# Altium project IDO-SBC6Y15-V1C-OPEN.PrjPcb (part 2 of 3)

## Sheet P06 SOM6ULX.SchDoc
size 594 x 420 mm
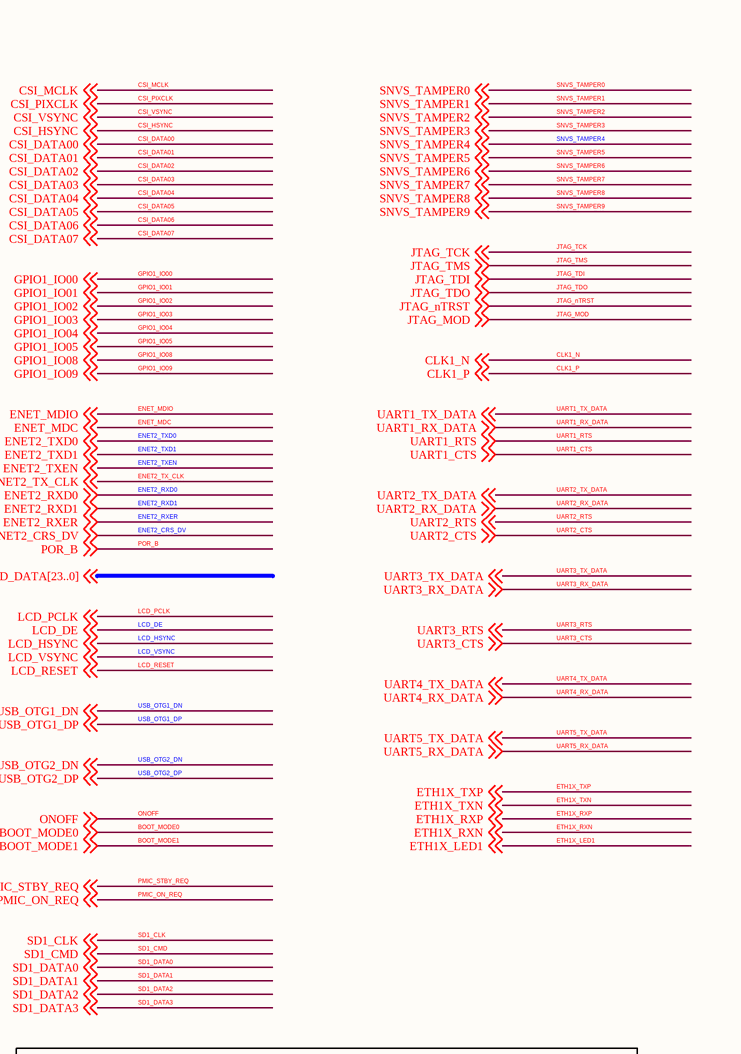
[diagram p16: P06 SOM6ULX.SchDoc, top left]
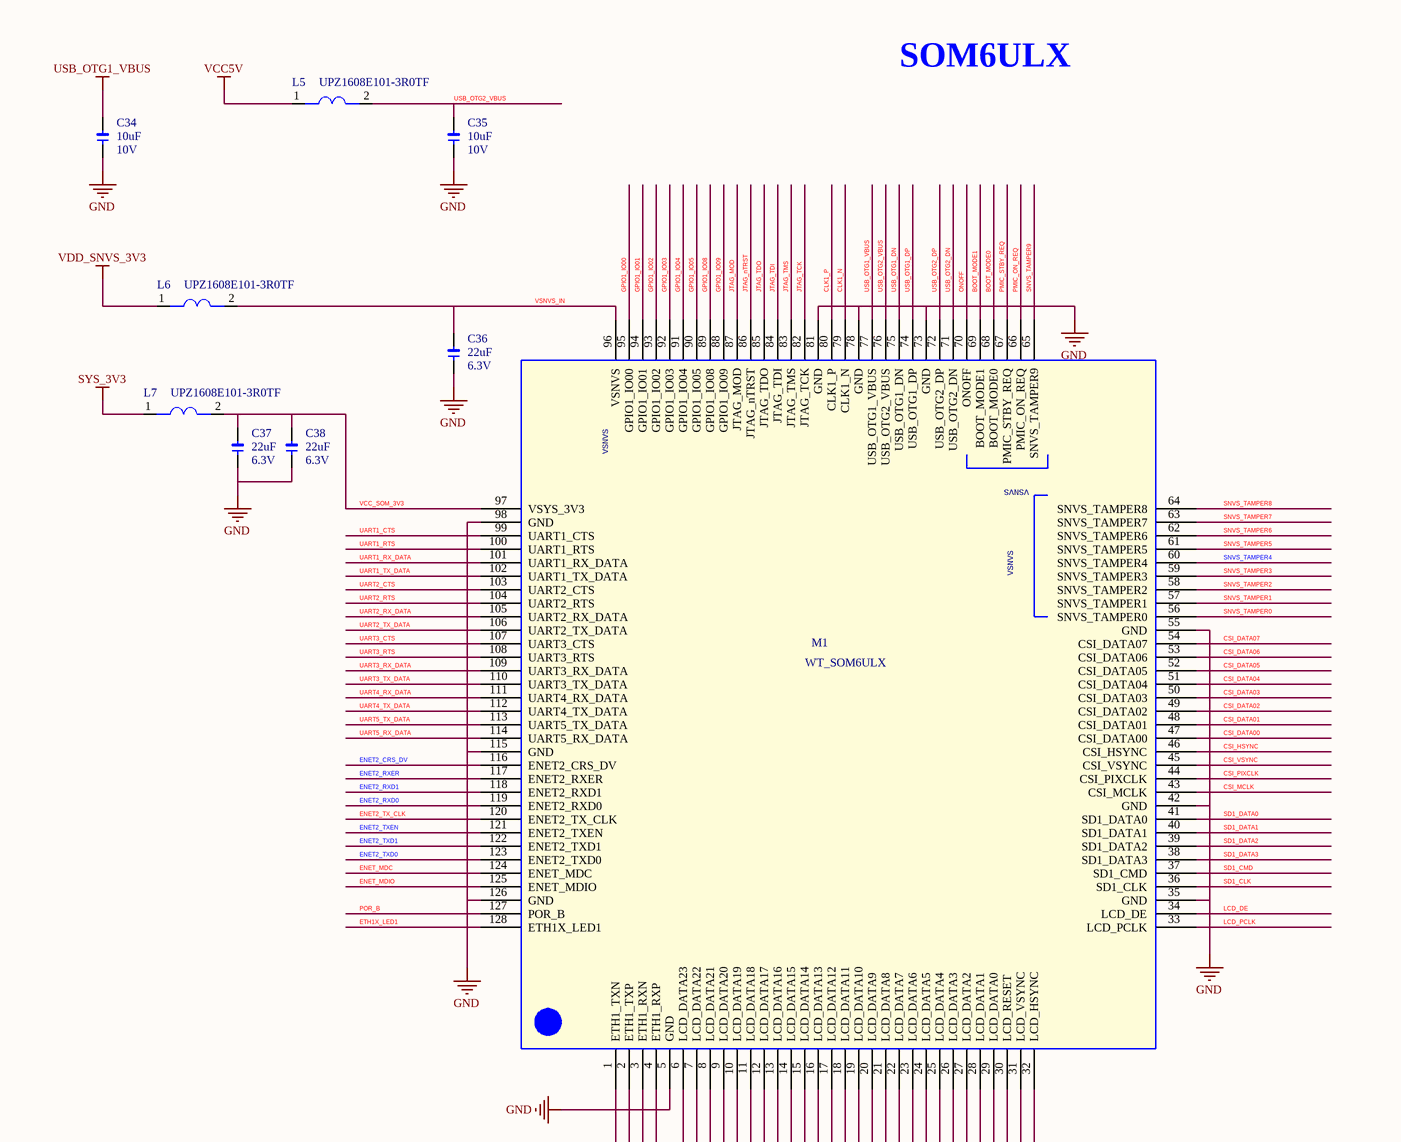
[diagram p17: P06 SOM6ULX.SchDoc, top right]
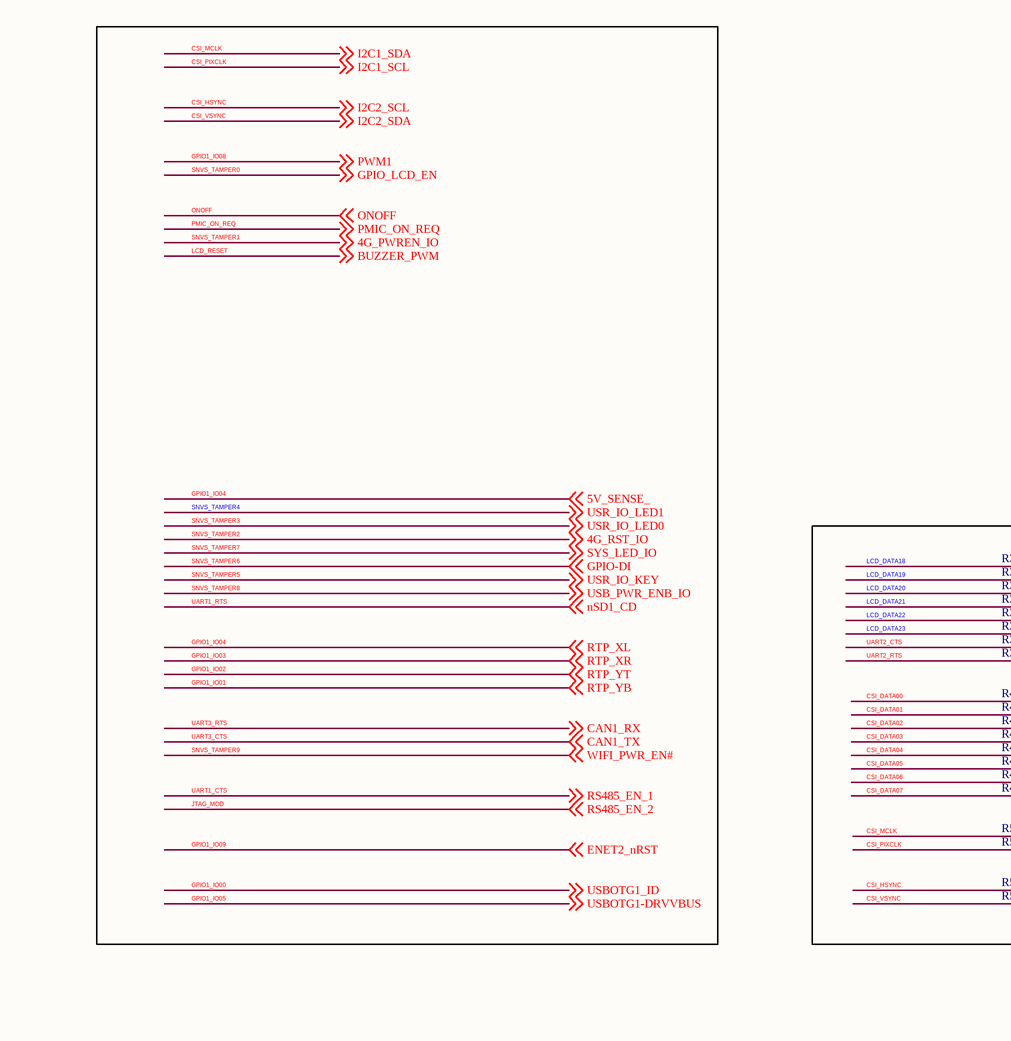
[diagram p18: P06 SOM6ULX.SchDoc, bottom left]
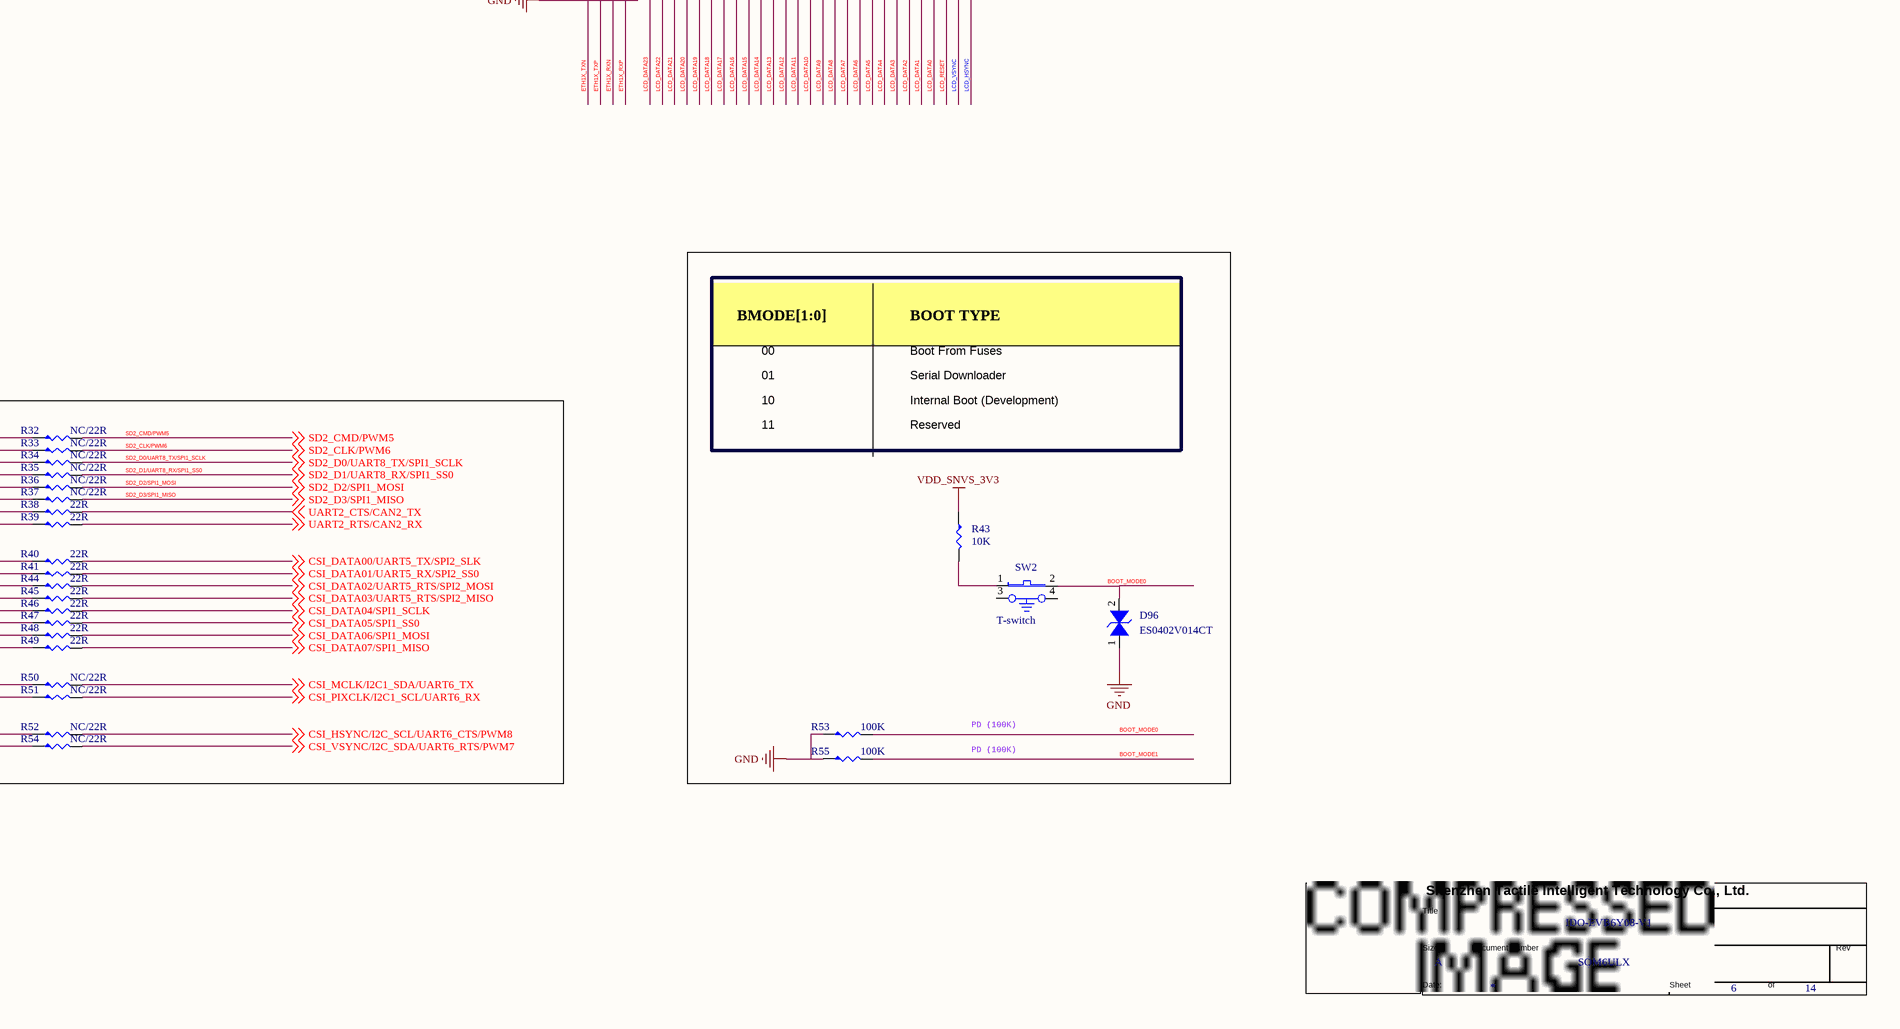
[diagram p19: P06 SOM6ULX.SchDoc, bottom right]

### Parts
(Parts that share a designator on the sheet are numbered #1, #2 ... from top to bottom, then left to right.)
*#6  Doc: SOM6ULX  Title: IDO-EVB6Y08-V1  Page Size: A  Page Number: 6  Page Count: 14  (hidden comment: TitleBlock1)  (graphical)
C34  10uF  DSC2: 10V  [1206]
C35  10uF  DSC2: 10V  [1206]
C36  22uF  DSC2: 6.3V  [1206]
C37  22uF  DSC2: 6.3V  [1206]
C38  22uF  DSC2: 6.3V  [1206]
D96  ES0402V014CT  [V0402]
L5  UPZ1608E101-3R0TF  [L0603]
L6  UPZ1608E101-3R0TF  [L0603]
L7  UPZ1608E101-3R0TF  [L0603]
M1  WT_SOM6ULX  [WT_SOM6ULX_LGA128]
R32  NC/22R  [R0402L]
R33  NC/22R  [R0402L]
R34  NC/22R  [R0402L]
R35  NC/22R  [R0402L]
R36  NC/22R  [R0402L]
R37  NC/22R  [R0402L]
R38  22R  [R0402L]
R39  22R  [R0402L]
R40  22R  [R0402L]
R41  22R  [R0402L]
R43  10K  [R0402L]
R44  22R  [R0402L]
R45  22R  [R0402L]
R46  22R  [R0402L]
R47  22R  [R0402L]
R48  22R  [R0402L]
R49  22R  [R0402L]
R50  NC/22R  [R0402L]
R51  NC/22R  [R0402L]
R52  NC/22R  [R0402L]
R53  100K  [R0402L]
R54  NC/22R  [R0402L]
R55  100K  [R0402L]
SW2  T-switch  [PB-SIDE-S-3x6]

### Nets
GND: C34.1 C35.1 C36.1 C37.1 C38.1 D96.1(I/O2) M1.5(GND) M1.35(GND) M1.42(GND) M1.55(GND) M1.73(GND) M1.78(GND) M1.81(GND) M1.98(GND) M1.115(GND) M1.126(GND) R53.1 R55.1
SYS_3V3: L7.1
USB_OTG1_VBUS: C34.2 M1.77(USB_OTG1_VBUS)
VCC5V: L5.1
VDD_SNVS_3V3: L6.1 R43.1
4G_PWREN_IO: M1.57(SNVS_TAMPER1) ; off-sheet 4G_PWREN_IO, off-sheet SNVS_TAMPER1  [also labelled SNVS_TAMPER1]  [project net 4G_POWER_EN]
4G_RST_IO: M1.58(SNVS_TAMPER2) ; off-sheet 4G_RST_IO, off-sheet SNVS_TAMPER2  [also labelled SNVS_TAMPER2]  [project net 4G_RST]
5V_SENSE_: M1.91(GPIO1_IO04) ; off-sheet RTP_XL, off-sheet GPIO1_IO04, off-sheet 5V_SENSE_  [also labelled GPIO1_IO04, RTP_XL]
BOOT_MODE0: D96.2(I/O1) M1.68(BOOT_MODE0) R53.2 SW2.2 ; off-sheet BOOT_MODE0
BOOT_MODE1: M1.69(BOOT_MODE1) R55.2 ; off-sheet BOOT_MODE1
BUZZER_PWM: M1.30(LCD_RESET) ; off-sheet BUZZER_PWM, off-sheet LCD_RESET  [also labelled LCD_RESET]
CAN1_RX: M1.108(UART3_RTS) ; off-sheet CAN1_RX, off-sheet UART3_RTS  [also labelled UART3_RTS]
CAN1_TX: M1.107(UART3_CTS) ; off-sheet CAN1_TX, off-sheet UART3_CTS  [also labelled UART3_CTS]
CLK1_N: M1.79(CLK1_N) ; off-sheet CLK1_N
CLK1_P: M1.80(CLK1_P) ; off-sheet CLK1_P
CSI_DATA00: M1.47(CSI_DATA00) R40.1 ; off-sheet CSI_DATA00
CSI_DATA00/UART5_TX/SPI2_SLK: R40.2 ; off-sheet CSI_DATA00/UART5_TX/SPI2_SLK
CSI_DATA01: M1.48(CSI_DATA01) R41.1 ; off-sheet CSI_DATA01
CSI_DATA01/UART5_RX/SPI2_SS0: R41.2 ; off-sheet CSI_DATA01/UART5_RX/SPI2_SS0
CSI_DATA02: M1.49(CSI_DATA02) R44.1 ; off-sheet CSI_DATA02
CSI_DATA02/UART5_RTS/SPI2_MOSI: R44.2 ; off-sheet CSI_DATA02/UART5_RTS/SPI2_MOSI
CSI_DATA03: M1.50(CSI_DATA03) R45.1 ; off-sheet CSI_DATA03
CSI_DATA03/UART5_RTS/SPI2_MISO: R45.2 ; off-sheet CSI_DATA03/UART5_RTS/SPI2_MISO
CSI_DATA04: M1.51(CSI_DATA04) R46.1 ; off-sheet CSI_DATA04
CSI_DATA04/SPI1_SCLK: R46.2 ; off-sheet CSI_DATA04/SPI1_SCLK
CSI_DATA05: M1.52(CSI_DATA05) R47.1 ; off-sheet CSI_DATA05
CSI_DATA05/SPI1_SS0: R47.2 ; off-sheet CSI_DATA05/SPI1_SS0
CSI_DATA06: M1.53(CSI_DATA06) R48.1 ; off-sheet CSI_DATA06
CSI_DATA06/SPI1_MOSI: R48.2 ; off-sheet CSI_DATA06/SPI1_MOSI
CSI_DATA07: M1.54(CSI_DATA07) R49.1 ; off-sheet CSI_DATA07
CSI_DATA07/SPI1_MISO: R49.2 ; off-sheet CSI_DATA07/SPI1_MISO
CSI_HSYNC: M1.46(CSI_HSYNC) R52.1 ; off-sheet I2C2_SCL, off-sheet CSI_HSYNC  [also labelled I2C2_SCL]
CSI_HSYNC/I2C_SCL/UART6_CTS/PWM8: R52.2 ; off-sheet CSI_HSYNC/I2C_SCL/UART6_CTS/PWM8
CSI_MCLK: M1.43(CSI_MCLK) R50.1 ; off-sheet I2C1_SDA, off-sheet CSI_MCLK  [also labelled I2C1_SDA]
CSI_MCLK/I2C1_SDA/UART6_TX: R50.2 ; off-sheet CSI_MCLK/I2C1_SDA/UART6_TX
CSI_PIXCLK: M1.44(CSI_PIXCLK) R51.1 ; off-sheet I2C1_SCL, off-sheet CSI_PIXCLK  [also labelled I2C1_SCL]
CSI_PIXCLK/I2C1_SCL/UART6_RX: R51.2 ; off-sheet CSI_PIXCLK/I2C1_SCL/UART6_RX
CSI_VSYNC: M1.45(CSI_VSYNC) R54.1 ; off-sheet I2C2_SDA, off-sheet CSI_VSYNC  [also labelled I2C2_SDA]
CSI_VSYNC/I2C_SDA/UART6_RTS/PWM7: R54.2 ; off-sheet CSI_VSYNC/I2C_SDA/UART6_RTS/PWM7
ENET2_CRS_DV: M1.116(ENET2_CRS_DV) ; off-sheet ENET2_CRS_DV
ENET2_nRST: M1.88(GPIO1_IO09) ; off-sheet ENET2_nRST, off-sheet GPIO1_IO09  [also labelled GPIO1_IO09]
ENET2_RXD0: M1.119(ENET2_RXD0) ; off-sheet ENET2_RXD0
ENET2_RXD1: M1.118(ENET2_RXD1) ; off-sheet ENET2_RXD1
ENET2_RXER: M1.117(ENET2_RXER) ; off-sheet ENET2_RXER
ENET2_TX_CLK: M1.120(ENET2_TX_CLK) ; off-sheet ENET2_TX_CLK
ENET2_TXD0: M1.123(ENET2_TXD0) ; off-sheet ENET2_TXD0
ENET2_TXD1: M1.122(ENET2_TXD1) ; off-sheet ENET2_TXD1
ENET2_TXEN: M1.121(ENET2_TXEN) ; off-sheet ENET2_TXEN
ENET_MDC: M1.124(ENET_MDC) ; off-sheet ENET_MDC
ENET_MDIO: M1.125(ENET_MDIO) ; off-sheet ENET_MDIO
ETH1X_LED1: M1.128(ETH1X_LED1) ; off-sheet ETH1X_LED1
ETH1X_RXN: M1.3(ETH1_RXN) ; off-sheet ETH1X_RXN
ETH1X_RXP: M1.4(ETH1_RXP) ; off-sheet ETH1X_RXP
ETH1X_TXN: M1.1(ETH1_TXN) ; off-sheet ETH1X_TXN
ETH1X_TXP: M1.2(ETH1_TXP) ; off-sheet ETH1X_TXP
GPIO1_IO00: M1.95(GPIO1_IO00) ; off-sheet USBOTG1_ID, off-sheet GPIO1_IO00  [also labelled USBOTG1_ID]
GPIO1_IO01: M1.94(GPIO1_IO01) ; off-sheet RTP_YB, off-sheet GPIO1_IO01  [also labelled RTP_YB]
GPIO1_IO02: M1.93(GPIO1_IO02) ; off-sheet RTP_YT, off-sheet GPIO1_IO02  [also labelled RTP_YT]
GPIO1_IO03: M1.92(GPIO1_IO03) ; off-sheet RTP_XR, off-sheet GPIO1_IO03  [also labelled RTP_XR]
GPIO1_IO05: M1.90(GPIO1_IO05) ; off-sheet USBOTG1-DRVVBUS, off-sheet GPIO1_IO05  [also labelled USBOTG1-DRVVBUS]
GPIO1_IO08: M1.89(GPIO1_IO08) ; off-sheet PWM1, off-sheet GPIO1_IO08  [also labelled PWM1]
GPIO-DI: M1.62(SNVS_TAMPER6) ; off-sheet GPIO-DI, off-sheet SNVS_TAMPER6  [also labelled SNVS_TAMPER6]
GPIO_LCD_EN: M1.56(SNVS_TAMPER0) ; off-sheet GPIO_LCD_EN, off-sheet SNVS_TAMPER0  [also labelled SNVS_TAMPER0]
JTAG_MOD: M1.87(JTAG_MOD) ; off-sheet RS485_EN_2, off-sheet JTAG_MOD  [also labelled RS485_EN_2]
JTAG_nTRST: M1.86(JTAG_nTRST) ; off-sheet JTAG_nTRST
JTAG_TCK: M1.82(JTAG_TCK) ; off-sheet JTAG_TCK
JTAG_TDI: M1.84(JTAG_TDI) ; off-sheet JTAG_TDI
JTAG_TDO: M1.85(JTAG_TDO) ; off-sheet JTAG_TDO
JTAG_TMS: M1.83(JTAG_TMS) ; off-sheet JTAG_TMS
LCD_DATA0: M1.29(LCD_DATA0)
LCD_DATA1: M1.28(LCD_DATA1)
LCD_DATA2: M1.27(LCD_DATA2)
LCD_DATA3: M1.26(LCD_DATA3)
LCD_DATA4: M1.25(LCD_DATA4)
LCD_DATA5: M1.24(LCD_DATA5)
LCD_DATA6: M1.23(LCD_DATA6)
LCD_DATA7: M1.22(LCD_DATA7)
LCD_DATA8: M1.21(LCD_DATA8)
LCD_DATA9: M1.20(LCD_DATA9)
LCD_DATA10: M1.19(LCD_DATA10)
LCD_DATA11: M1.18(LCD_DATA11)
LCD_DATA12: M1.17(LCD_DATA12)
LCD_DATA13: M1.16(LCD_DATA13)
LCD_DATA14: M1.15(LCD_DATA14)
LCD_DATA15: M1.14(LCD_DATA15)
LCD_DATA16: M1.13(LCD_DATA16)
LCD_DATA17: M1.12(LCD_DATA17)
LCD_DATA18: M1.11(LCD_DATA18) R32.1
LCD_DATA19: M1.10(LCD_DATA19) R33.1
LCD_DATA20: M1.9(LCD_DATA20) R34.1
LCD_DATA21: M1.8(LCD_DATA21) R35.1
LCD_DATA22: M1.7(LCD_DATA22) R36.1
LCD_DATA23: M1.6(LCD_DATA23) R37.1
LCD_DE: M1.34(LCD_DE) ; off-sheet LCD_DE
LCD_HSYNC: M1.32(LCD_HSYNC) ; off-sheet LCD_HSYNC
LCD_PCLK: M1.33(LCD_PCLK) ; off-sheet LCD_PCLK
LCD_VSYNC: M1.31(LCD_VSYNC) ; off-sheet LCD_VSYNC
ONOFF: M1.70(ONOFF) ; off-sheet ONOFF
PMIC_ON_REQ: M1.66(PMIC_ON_REQ) ; off-sheet PMIC_ON_REQ
PMIC_STBY_REQ: M1.67(PMIC_STBY_REQ) ; off-sheet PMIC_STBY_REQ
POR_B: M1.127(POR_B) ; off-sheet POR_B
RS485_EN_1: M1.99(UART1_CTS) ; off-sheet RS485_EN_1, off-sheet UART1_CTS  [also labelled UART1_CTS]
SD1_CLK: M1.36(SD1_CLK) ; off-sheet SD1_CLK
SD1_CMD: M1.37(SD1_CMD) ; off-sheet SD1_CMD
SD1_DATA0: M1.41(SD1_DATA0) ; off-sheet SD1_DATA0
SD1_DATA1: M1.40(SD1_DATA1) ; off-sheet SD1_DATA1
SD1_DATA2: M1.39(SD1_DATA2) ; off-sheet SD1_DATA2
SD1_DATA3: M1.38(SD1_DATA3) ; off-sheet SD1_DATA3
SD2_CLK/PWM6: R33.2 ; off-sheet SD2_CLK/PWM6
SD2_CMD/PWM5: R32.2 ; off-sheet SD2_CMD/PWM5
SD2_D0/UART8_TX/SPI1_SCLK: R34.2 ; off-sheet SD2_D0/UART8_TX/SPI1_SCLK
SD2_D1/UART8_RX/SPI1_SS0: R35.2 ; off-sheet SD2_D1/UART8_RX/SPI1_SS0
SD2_D2/SPI1_MOSI: R36.2 ; off-sheet SD2_D2/SPI1_MOSI
SD2_D3/SPI1_MISO: R37.2 ; off-sheet SD2_D3/SPI1_MISO
SNVS_TAMPER3: M1.59(SNVS_TAMPER3) ; off-sheet USR_IO_LED0, off-sheet SNVS_TAMPER3  [also labelled USR_IO_LED0]
SNVS_TAMPER4: M1.60(SNVS_TAMPER4) ; off-sheet USR_IO_LED1, off-sheet SNVS_TAMPER4  [also labelled USR_IO_LED1]
SNVS_TAMPER5: M1.61(SNVS_TAMPER5) ; off-sheet USR_IO_KEY, off-sheet SNVS_TAMPER5  [also labelled USR_IO_KEY]  [project net IO_KEY]
SNVS_TAMPER7: M1.63(SNVS_TAMPER7) ; off-sheet SYS_LED_IO, off-sheet SNVS_TAMPER7  [also labelled SYS_LED_IO]
SNVS_TAMPER8: M1.64(SNVS_TAMPER8) ; off-sheet USB_PWR_ENB_IO, off-sheet SNVS_TAMPER8  [also labelled USB_PWR_ENB_IO]
SNVS_TAMPER9: M1.65(SNVS_TAMPER9) ; off-sheet WIFI_PWR_EN#, off-sheet SNVS_TAMPER9  [also labelled WIFI_PWR_EN#]
UART1_RTS: M1.100(UART1_RTS) ; off-sheet nSD1_CD, off-sheet UART1_RTS  [also labelled nSD1_CD]
UART1_RX_DATA: M1.101(UART1_RX_DATA) ; off-sheet UART1_RX_DATA
UART1_TX_DATA: M1.102(UART1_TX_DATA) ; off-sheet UART1_TX_DATA
UART2_CTS: M1.103(UART2_CTS) R38.1 ; off-sheet UART2_CTS
UART2_CTS/CAN2_TX: R38.2 ; off-sheet UART2_CTS/CAN2_TX
UART2_RTS: M1.104(UART2_RTS) R39.1 ; off-sheet UART2_RTS
UART2_RTS/CAN2_RX: R39.2 ; off-sheet UART2_RTS/CAN2_RX
UART2_RX_DATA: M1.105(UART2_RX_DATA) ; off-sheet UART2_RX_DATA
UART2_TX_DATA: M1.106(UART2_TX_DATA) ; off-sheet UART2_TX_DATA
UART3_RX_DATA: M1.109(UART3_RX_DATA) ; off-sheet UART3_RX_DATA
UART3_TX_DATA: M1.110(UART3_TX_DATA) ; off-sheet UART3_TX_DATA
UART4_RX_DATA: M1.111(UART4_RX_DATA) ; off-sheet UART4_RX_DATA  [project net RS485X1_DOUT]
UART4_TX_DATA: M1.112(UART4_TX_DATA) ; off-sheet UART4_TX_DATA  [project net RS485X1_DIN]
UART5_RX_DATA: M1.114(UART5_RX_DATA) ; off-sheet UART5_RX_DATA  [project net RS485X2_DOUT]
UART5_TX_DATA: M1.113(UART5_TX_DATA) ; off-sheet UART5_TX_DATA  [project net RS485X2_DIN]
USB_OTG1_DN: M1.75(USB_OTG1_DN) ; off-sheet USB_OTG1_DN
USB_OTG1_DP: M1.74(USB_OTG1_DP) ; off-sheet USB_OTG1_DP
USB_OTG2_DN: M1.71(USB_OTG2_DN) ; off-sheet USB_OTG2_DN
USB_OTG2_DP: M1.72(USB_OTG2_DP) ; off-sheet USB_OTG2_DP
USB_OTG2_VBUS: C35.2 L5.2 M1.76(USB_OTG2_VBUS)
VCC_SOM_3V3: C37.2 C38.2 L7.2 M1.97(VSYS_3V3)
VSNVS_IN: C36.2 L6.2 M1.96(VSNVS)
NetR43_2: R43.2 SW2.1

Not connected (* = marked no-connect by the designer): SW2 3 4

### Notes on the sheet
- SOM6ULX
- BMODE[1:0]
- BOOT TYPE
- 00
- 01
- 10
- Boot From Fuses
- Serial Downloader
- Internal Boot (Development)
- 11
- Reserved
- PD (100K)

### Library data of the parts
C34 = C-0603: Manufacture: 三星¦国巨¦村田; Part Name: 贴片电容; Part Number: C020102120071; ID: 71; DSC3: X5R; DSC1: ±20%; ERP Number: 1010200076; PCB Footprint: C0603L
C35 = C-0603: Part Number: C020102120071; Part Name: 贴片电容; Manufacture: 三星¦国巨¦村田; ERP Number: 1010200076; DSC1: ±20%; DSC3: X5R; ID: 71; PCB Footprint: C0603L
C36-C38 = C-0603: Manufacture: 三星¦国巨¦村田; Part Name: 贴片电容; Part Number: C020102120072; ID: 72; DSC3: X5R; DSC1: ±20%; ERP Number: 1010200133; PCB Footprint: C0603L
D96 = DI-ESD: ESD 0402; Part Number: C040502250002; Manufacture P/N: MLVG04021R0UV18; Manufacturer: INPAQ; Manufacture: AEM; PN Type: Varistor; ERP Number: 1010800023; DSC1: 双向; DSC2: Vdc=14V; DSC3: Vbr=300V; DSC4: Vc=30V; DSC5: Cj=0.25pF; ID: 2
L5 L7 = FB-0603: SMD Multilayer Ferrite Chip Bead,3A,30Ohm,0.03R; Manufacturer: SUNLORD; Manufacture2 P/N: PBY160808T-400Y-N; Manufacture P/N: PZ1608D300-3R0TF; Part Number: C060502370005; Manufacture: 顺络; Part Name: 贴片磁珠; PN Type: SMD FERRITE BEAD; ID: 5; DSC4: 电源线; DSC3: DCR=30mΩ; DSC1: 100Ω@100MHz; ERP Number: 1010200207
L6 = FB-0603: SMD Multilayer Ferrite Chip Bead,3A,30Ohm,0.03R; Manufacturer: SUNLORD; Manufacture2 P/N: PBY160808T-400Y-N; Manufacture P/N: PZ1608D300-3R0TF; Part Number: C060502370005; Part Name: 贴片磁珠; Manufacture: 顺络; PN Type: SMD FERRITE BEAD; ERP Number: 1010200207; DSC1: 100Ω@100MHz; DSC3: DCR=30mΩ; DSC4: 电源线; ID: 5
M1 = IDO-SOM6Y08
R32-R37 R40 R41 R44-R51 = R-0402: Part Number: C011002080552; Part Name: 贴片电阻; ID: 552; DSC2: 1/16W; DSC1: ±1%
R38 R39 R52 R54 = R-0402: Part Name: 贴片电阻; Part Number: C011002080552; DSC1: ±1%; DSC2: 1/16W; ID: 552
R43 = R-0402: Part Name: 贴片电阻; Part Number: C011002080856; ERP Number: 1010200140; DSC1: ±1%; DSC2: 1/16W; ID: 856
R53 R55 = R-0402: Part Number: C011002080976; Part Name: 贴片电阻; ID: 976; DSC2: 1/16W; DSC1: ±1%; ERP Number: 1010200137
SW2 = SW-TS36CA: Part Number: C180102690002; Part Name: 轻触开关; DSC1: 轻触开关 侧键 贴片 带定位柱; DSC2: SMD,3.5*7.7mm; DSC3: TS36CA-0.7(首韩); DSC4: TSA365G00D-250(博瑞泰); ID: 2

## Sheet P07 SD_RTC.SchDoc
size 594 x 420 mm
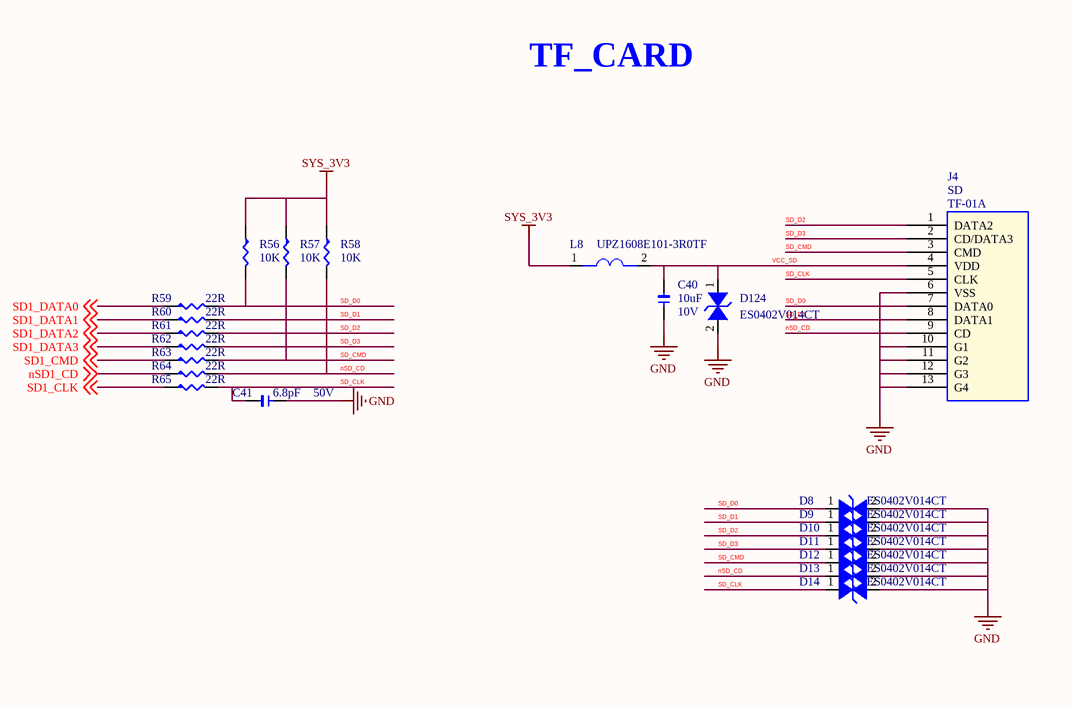
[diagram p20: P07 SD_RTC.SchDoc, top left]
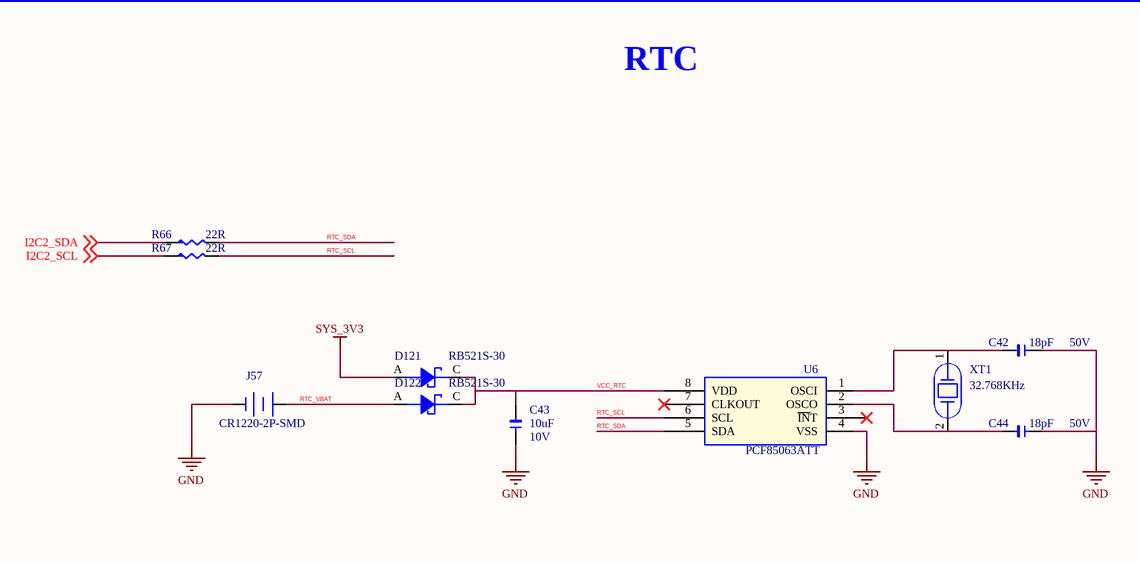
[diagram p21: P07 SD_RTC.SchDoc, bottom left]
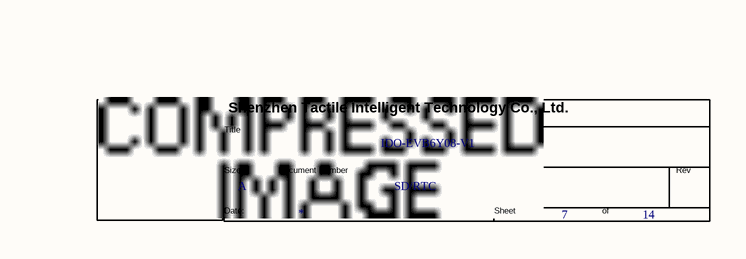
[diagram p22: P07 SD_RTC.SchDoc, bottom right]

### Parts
(Parts that share a designator on the sheet are numbered #1, #2 ... from top to bottom, then left to right.)
*#7  Doc: SD/RTC  Title: IDO-EVB6Y08-V1  Page Size: A  Page Number: 7  Page Count: 14  (hidden comment: TitleBlock1)  (graphical)
C40  10uF  DSC2: 10V  [1206]
C41  6.8pF  DSC2: 50V  [1206]
C42  18pF  DSC2: 50V  [1206]
C43  10uF  DSC2: 10V  [1206]
C44  18pF  DSC2: 50V  [1206]
D8  ES0402V014CT  [V0402]
D9  ES0402V014CT  [V0402]
D10  ES0402V014CT  [V0402]
D11  ES0402V014CT  [V0402]
D12  ES0402V014CT  [V0402]
D13  ES0402V014CT  [V0402]
D14  ES0402V014CT  [V0402]
D121  RB521S-30  [SOD523]
D122  RB521S-30  [SOD523]
D124  ES0402V014CT  [V0402]
J4  SD  [TF-01A]
J57  CR1220-2P-SMD  [CR1220-2P-SMD]
L8  UPZ1608E101-3R0TF  [L0603]
R56  10K  [R0402L]
R57  10K  [R0402L]
R58  10K  [R0402L]
R59  22R  [R0402L]
R60  22R  [R0402L]
R61  22R  [R0402L]
R62  22R  [R0402L]
R63  22R  [R0402L]
R64  22R  [R0402L]
R65  22R  [R0402L]
R66  22R  [R0402L]
R67  22R  [R0402L]
U6  PCF85063ATT  [PCF85063ATT-TSSOP8]
XT1  32.768KHz  [XTAL_32X15_2P]

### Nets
GND: C40.1 C41.1 C42.1 C43.1 C44.1 D8.2(I/O1) D9.2(I/O1) D10.2(I/O1) D11.2(I/O1) D12.2(I/O1) D13.2(I/O1) D14.2(I/O1) D124.2(I/O1) J4.6(VSS) J4.10(G1) J4.11(G2) J4.12(G3) J4.13(G4) J57.2(-) U6.4(VSS)
SYS_3V3: D121.A L8.1 R56.1 R57.1 R58.1
I2C2_SCL: R67.1 ; off-sheet I2C2_SCL  [project net CSI_HSYNC]
I2C2_SDA: R66.1 ; off-sheet I2C2_SDA  [project net CSI_VSYNC]
nSD1_CD: R64.1 ; off-sheet nSD1_CD  [project net UART1_RTS]
nSD_CD: D13.1(I/O2) J4.9(CD) R58.2 R64.2
RTC_SCL: R67.2 U6.6(SCL)
RTC_SDA: R66.2 U6.5(SDA)
RTC_VBAT: D122.A J57.1(+)
SD1_CLK: R65.1 ; off-sheet SD1_CLK
SD1_CMD: R63.1 ; off-sheet SD1_CMD
SD1_DATA0: R59.1 ; off-sheet SD1_DATA0
SD1_DATA1: R60.1 ; off-sheet SD1_DATA1
SD1_DATA2: R61.1 ; off-sheet SD1_DATA2
SD1_DATA3: R62.1 ; off-sheet SD1_DATA3
SD_CLK: C41.2 D14.1(I/O2) J4.5(CLK) R65.2
SD_CMD: D12.1(I/O2) J4.3(CMD) R57.2 R63.2
SD_D0: D8.1(I/O2) J4.7(DATA0) R56.2 R59.2
SD_D1: D9.1(I/O2) J4.8(DATA1) R60.2
SD_D2: D10.1(I/O2) J4.1(DATA2) R61.2
SD_D3: D11.1(I/O2) J4.2(CD/DATA3) R62.2
VCC_RTC: C43.2 D121.C D122.C U6.8(VDD)
VCC_SD: C40.2 D124.1(I/O2) J4.4(VDD) L8.2
NetC42_2: C42.2 U6.1(OSCI) XT1.1
NetC44_2: C44.2 U6.2(OSCO) XT1.2

Not connected (* = marked no-connect by the designer): U6 3(~{IN}T)* 7(CLKOUT)*

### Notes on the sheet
- TF_CARD
- RTC

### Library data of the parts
C40 = C-0603: as C35 on sheet P06 SOM6ULX
C41 = C-0402: Part Number: C020102120018; Part Name: 贴片电容; Manufacture: 三星¦国巨¦村田; PCB Footprint: C0402L; ERP Number: 1010200056; DSC1: ±0.25PF; DSC3: C0G; ID: 18
C42 C44 = C-0402: Manufacture: 三星¦国巨¦村田; Part Name: 贴片电容; Part Number: C020102120027; PCB Footprint: C0402L; ID: 27; DSC3: C0G; DSC1: ±5%; ERP Number: 1010200091
C43 = C-0603: Manufacture: 三星¦国巨¦村田; Part Name: 贴片电容; Part Number: C020102120071; PCB Footprint: C0603L; ID: 71; DSC3: X5R; DSC1: ±20%; ERP Number: 1010200076
D8-D12 = DI-ESD: ESD 0402; Part Number: C040502250002; Manufacture P/N: MLVG04021R0UV18; Manufacturer: INPAQ; Manufacture: AEM; PN Type: Varistor; ID: 2; DSC5: Cj=0.25pF; DSC4: Vc=30V; DSC3: Vbr=300V; DSC2: Vdc=14V; DSC1: 双向; ERP Number: 1010800023
D13 D14 D124 = DI-ESD: as D96 on sheet P06 SOM6ULX
D121 D122 = DI-XI-S: Part Number: C040202220015; Part Name: 肖特基二级管; Manufacture: 长电; CLASS: IC; ERP Number: 1010800004; DSC1: VR=30V; DSC2: IF=200mA; DSC3: VF=100mV/10mA; DSC4: IR=30uA; ID: 15; Solder: 量产
J4 = J-TF-01A: Part Name: SD卡座; Part Number: J080102980002; ID: 2; DSC4: TF-01A(韩荣); DSC3: 贴片; DSC1: TF卡座 自弹式
J57 = RTC-CR1220-2P-SMD: Part Name: 电池座; Part Number: J100303030001; ID: 4; DSC3: 贴片; DSC1: CR1220电池座 贴片 双定位柱; ERP Number: 1040100045
L8 = FB-0603: as L5 on sheet P06 SOM6ULX
R56-R58 = R-0402: Part Number: C011002080856; Part Name: 贴片电阻; ID: 856; DSC2: 1/16W; DSC1: ±1%; ERP Number: 1010200140
R59 R66 R67 = R-0402: as R32-R37 on sheet P06 SOM6ULX
R60-R65 = R-0402: as R38 on sheet P06 SOM6ULX
U6 = U-PCF85063ATT: Manufacture: NXP; Part Name: RTC芯片; Part Number: C110203283829; ID: 14; DSC3: -40℃~+85℃; DSC2: TSSOP8; DSC1: RTC,I2C, VCC=0.9-5.5V
XT1 = XTAL-2P: Manufacture: 泰晶; Part Number: C050102290002; Part Name: 贴片无源晶振; CLASS: IC; ID: 2; DSC5: 3.2*1.5mm 2P; DSC4: -40℃~+85℃; DSC3: 12.5pF; DSC2: ±20ppm; DSC1: 70kΩ

## Sheet P08 USB.SchDoc
size 594 x 420 mm
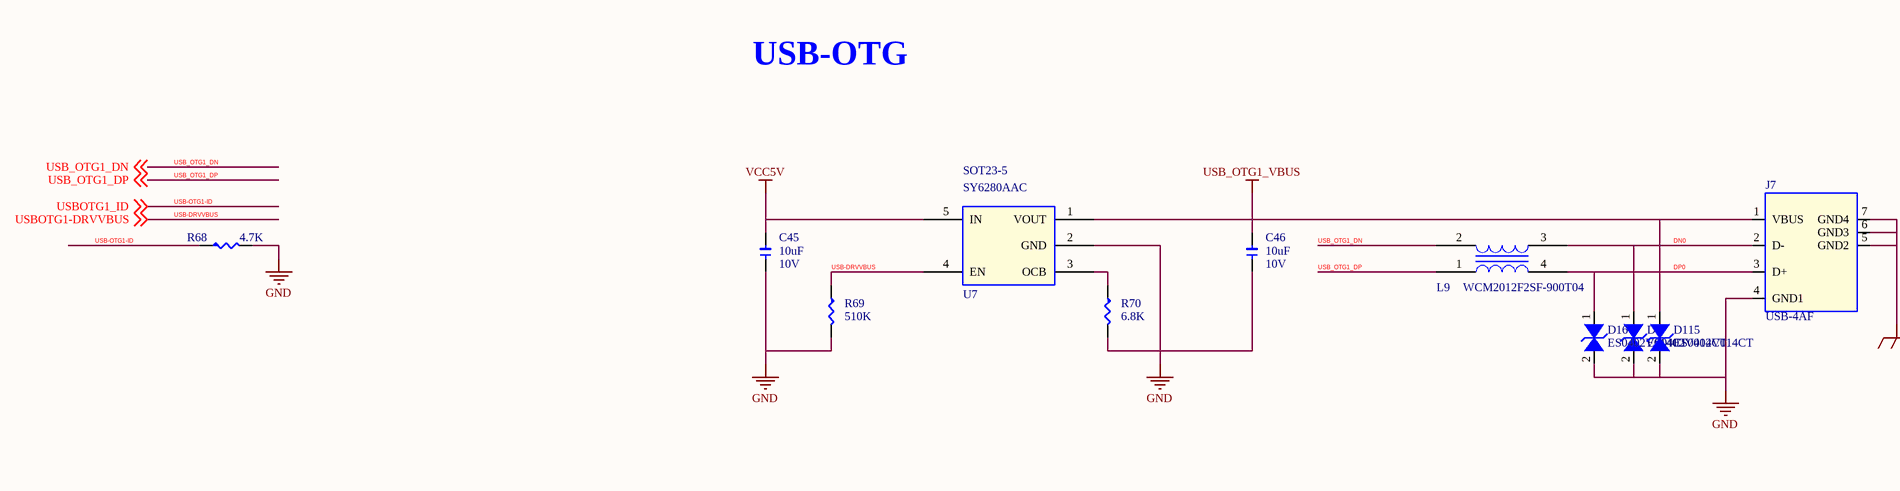
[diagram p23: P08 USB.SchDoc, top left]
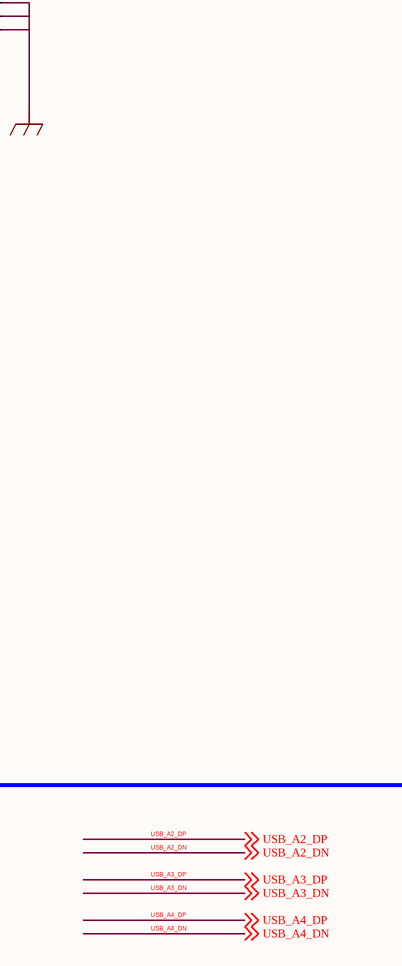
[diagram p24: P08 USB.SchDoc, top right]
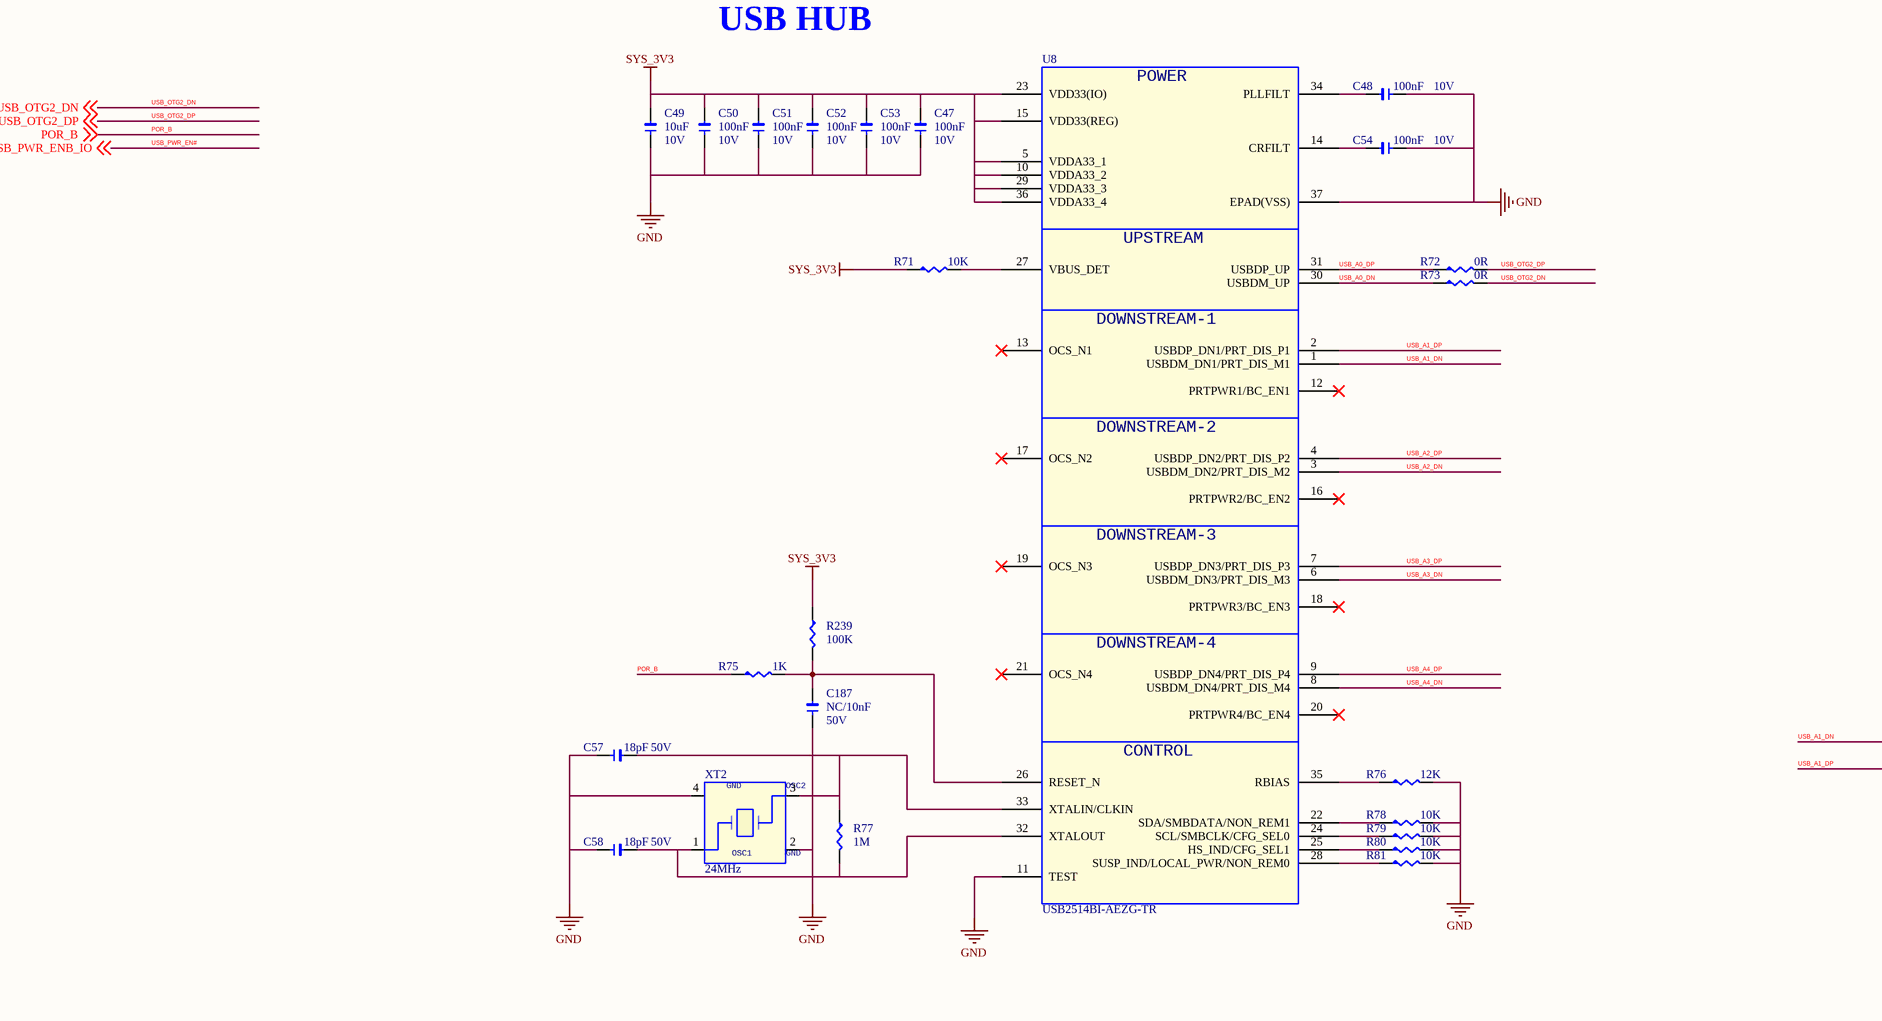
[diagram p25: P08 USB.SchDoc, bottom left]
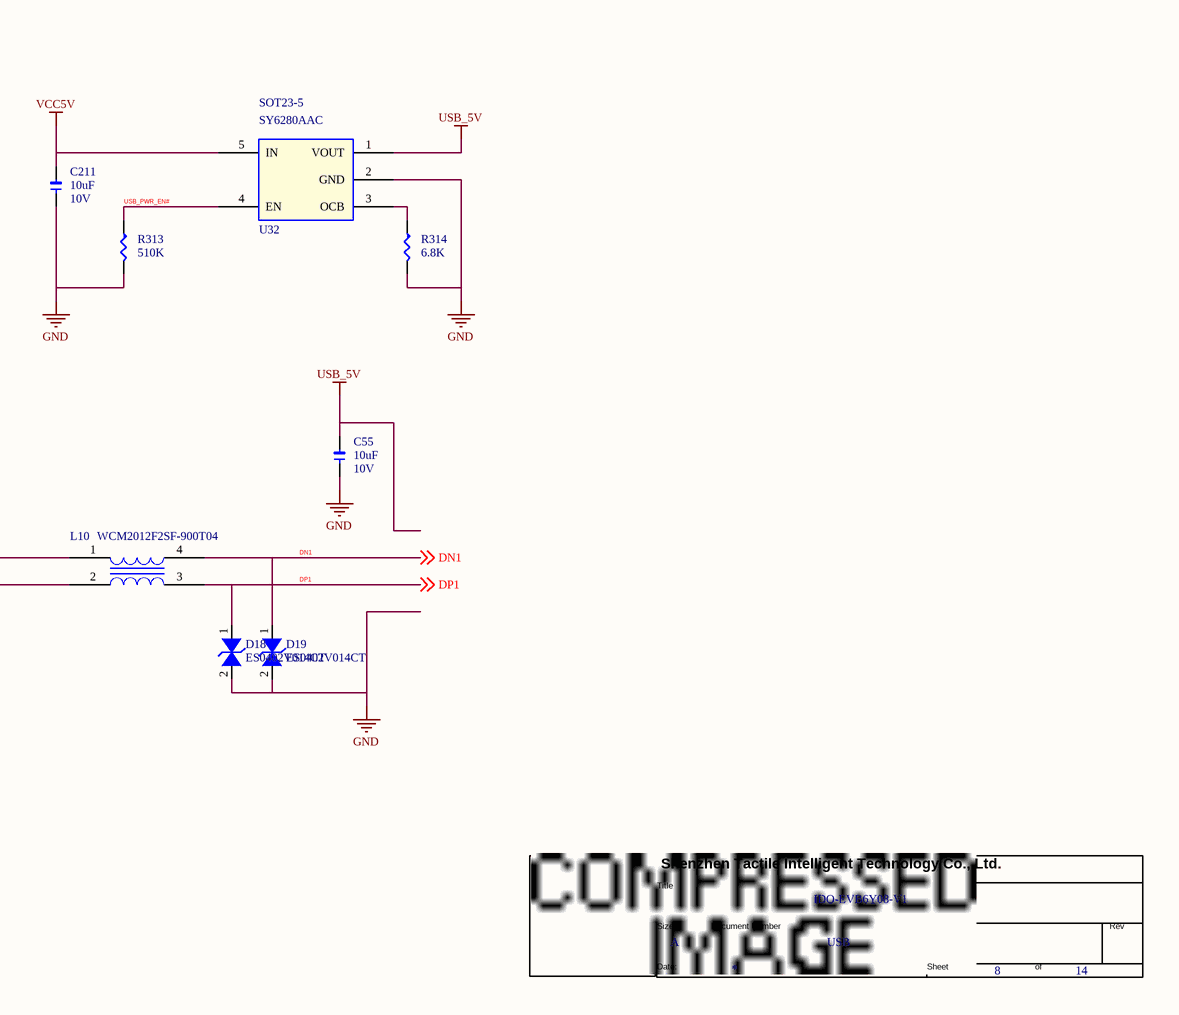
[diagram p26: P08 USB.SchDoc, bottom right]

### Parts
(Parts that share a designator on the sheet are numbered #1, #2 ... from top to bottom, then left to right.)
*#8  Doc: USB  Title: IDO-EVB6Y08-V1  Page Size: A  Page Number: 8  Page Count: 14  (hidden comment: TitleBlock1)  (graphical)
C45  10uF  DSC2: 10V  [1206]
C46  10uF  DSC2: 10V  [1206]
C47  100nF  DSC2: 10V  [1206]
C48  100nF  DSC2: 10V  [1206]
C49  10uF  DSC2: 10V  [1206]
C50  100nF  DSC2: 10V  [1206]
C51  100nF  DSC2: 10V  [1206]
C52  100nF  DSC2: 10V  [1206]
C53  100nF  DSC2: 10V  [1206]
C54  100nF  DSC2: 10V  [1206]
C55  10uF  DSC2: 10V  [1206]
C57  18pF  DSC2: 50V  [1206]
C58  18pF  DSC2: 50V  [1206]
C187  NC/10nF  DSC2: 50V  [1206]
C211  10uF  DSC2: 10V  [1206]
D16  ES0402V014CT  [V0402]
D17  ES0402V014CT  [V0402]
D18  ES0402V014CT  [V0402]
D19  ES0402V014CT  [V0402]
D115  ES0402V014CT  [V0402]
J7  USB-4AF  [USB-4AF-DIP-3W]
L9  WCM2012F2SF-900T04  [CMLS-ACM2012]
L10  WCM2012F2SF-900T04  [CMLS-ACM2012]
R68  4.7K  [R0402L]
R69  510K  [R0402L]
R70  6.8K  [R0402L]
R71  10K  [R0402L]
R72  0R  [R0402L]
R73  0R  [R0402L]
R75  1K  [R0402L]
R76  12K  [R0402L]
R77  1M  [R0402L]
R78  10K  [R0402L]
R79  10K  [R0402L]
R80  10K  [R0402L]
R81  10K  [R0402L]
R239  100K  [R0402L]
R313  510K  [R0402L]
R314  6.8K  [R0402L]
U7  SY6280AAC  [SOT23-5]
U8  USB2514BI-AEZG-TR  [USB2514BI-QFN-36]
U32  SY6280AAC  [SOT23-5]
XT2  24MHz  [xtal_32x25_4p]

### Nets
GND: C45.1 C46.1 C47.1 C48.1 C49.1 C50.1 C51.1 C52.1 C53.1 C54.1 C55.1 C57.1 C58.1 C187.1 C211.1 D16.2(I/O1) D17.2(I/O1) D18.2(I/O1) D19.2(I/O1) D115.2(I/O1) J7.4(GND1) R68.2 R69.2 R70.2 R76.2 R78.2 R79.2 R80.2 R81.2 R313.2 R314.2 U7.2(GND) U8.11(TEST) U8.37(EPAD(VSS)) U32.2(GND) XT2.2 XT2.4
GND_EARTH: J7.5(GND2) J7.6(GND3) J7.7(GND4)
SYS_3V3: C47.2 C49.2 C50.2 C51.2 C52.2 C53.2 R71.1 R239.1 U8.5(VDDA33_1) U8.10(VDDA33_2) U8.15(VDD33(REG)) U8.23(VDD33(IO)) U8.29(VDDA33_3) U8.36(VDDA33_4)
USB_5V: C55.2 U32.1(VOUT)
USB_OTG1_VBUS: C46.2 D115.1(I/O2) J7.1(VBUS) U7.1(VOUT)
VCC5V: C45.2 C211.2 U7.5(IN) U32.5(IN)
DN0: D17.1(I/O2) J7.2(D-) L9.3
DN1: D19.1(I/O2) L10.4 ; off-sheet DN1
DP0: D16.1(I/O2) J7.3(D+) L9.4
DP1: D18.1(I/O2) L10.3 ; off-sheet DP1
POR_B: R75.1 ; off-sheet POR_B
USB-DRVVBUS: R69.1 U7.4(EN) ; off-sheet USBOTG1-DRVVBUS  [also labelled USBOTG1-DRVVBUS]  [project net GPIO1_IO05]
USB-OTG1-ID: R68.1 ; off-sheet USBOTG1_ID  [also labelled USBOTG1_ID]  [project net GPIO1_IO00]
USB_A0_DN: R73.1 U8.30(USBDM_UP)
USB_A0_DP: R72.1 U8.31(USBDP_UP)
USB_A1_DN: L10.1 U8.1(USBDM_DN1/PRT_DIS_M1)
USB_A1_DP: L10.2 U8.2(USBDP_DN1/PRT_DIS_P1)
USB_A2_DN: U8.3(USBDM_DN2/PRT_DIS_M2) ; off-sheet USB_A2_DN
USB_A2_DP: U8.4(USBDP_DN2/PRT_DIS_P2) ; off-sheet USB_A2_DP
USB_A3_DN: U8.6(USBDM_DN3/PRT_DIS_M3) ; off-sheet USB_A3_DN
USB_A3_DP: U8.7(USBDP_DN3/PRT_DIS_P3) ; off-sheet USB_A3_DP
USB_A4_DN: U8.8(USBDM_DN4/PRT_DIS_M4) ; off-sheet USB_A4_DN
USB_A4_DP: U8.9(USBDP_DN4/PRT_DIS_P4) ; off-sheet USB_A4_DP
USB_OTG1_DN: L9.2 ; off-sheet USB_OTG1_DN
USB_OTG1_DP: L9.1 ; off-sheet USB_OTG1_DP
USB_OTG2_DN: R73.2 ; off-sheet USB_OTG2_DN
USB_OTG2_DP: R72.2 ; off-sheet USB_OTG2_DP
USB_PWR_EN#: R313.1 U32.4(EN) ; off-sheet USB_PWR_ENB_IO  [also labelled USB_PWR_ENB_IO]  [project net SNVS_TAMPER8]
NetC48_2: C48.2 U8.34(PLLFILT)
NetC54_2: C54.2 U8.14(CRFILT)
NetC57_2: C57.2 R77.1 U8.33(XTALIN/CLKIN) XT2.3
NetC58_2: C58.2 R77.2 U8.32(XTALOUT) XT2.1
NetC187_2: C187.2 R75.2 R239.2 U8.26(RESET_N)
NetR70_1: R70.1 U7.3(OCB)
NetR71_2: R71.2 U8.27(VBUS_DET)
NetR76_1: R76.1 U8.35(RBIAS)
NetR78_1: R78.1 U8.22(SDA/SMBDATA/NON_REM1)
NetR79_1: R79.1 U8.24(SCL/SMBCLK/CFG_SEL0)
NetR80_1: R80.1 U8.25(HS_IND/CFG_SEL1)
NetR81_1: R81.1 U8.28(SUSP_IND/LOCAL_PWR/NON_REM0)
NetR314_1: R314.1 U32.3(OCB)

Not connected (* = marked no-connect by the designer): U8 12(PRTPWR1/BC_EN1)* 13(OCS_N1)* 16(PRTPWR2/BC_EN2)* 17(OCS_N2)* 18(PRTPWR3/BC_EN3)* 19(OCS_N3)* 20(PRTPWR4/BC_EN4)* 21(OCS_N4)*

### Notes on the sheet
- USB-OTG
- USB HUB

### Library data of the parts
C45 C49 = C-0603: Part Number: C020102120071; Part Name: 贴片电容; Manufacture: 三星¦国巨¦村田; PCB Footprint: C0603L; ERP Number: 1010200076; DSC1: ±20%; DSC3: X5R; ID: 71
C46 C55 = C-0603: as C43 on sheet P07 SD_RTC
C47 C50-C54 = C-0402: Manufacture: 三星¦国巨¦村田; Part Name: 贴片电容; Part Number: C020102120060; PCB Footprint: C0402L; ID: 60; DSC3: X7R; DSC1: ±10%
C48 = C-0402: Part Number: C020102120060; Part Name: 贴片电容; Manufacture: 三星¦国巨¦村田; PCB Footprint: C0402L; DSC1: ±10%; DSC3: X7R; ID: 60
C57 C58 = C-0402: as C42 on sheet P07 SD_RTC
C187 = C-0402: Manufacture: 三星¦国巨¦村田; Part Name: 贴片电容; Part Number: C020102120057; ID: 57; DSC3: X7R; DSC1: ±10%; ERP Number: 1010200077; PCB Footprint: C0402L
C211 = C-0603: as C35 on sheet P06 SOM6ULX
D16-D19 = DI-ESD: as D8-D12 on sheet P07 SD_RTC
D115 = DI-ESD: as D96 on sheet P06 SOM6ULX
J7 = J-USB-4AF-DIP-W-3_1: micro USB连接器; Part Number: J060102960007; ID: 7; DSC4: C42684(LC); DSC3: 通孔弯针; DSC2: 10.4*5.7mm*13.1; DSC1: USB AF 90度 侧插 铁壳短体10.4 无卷边 白胶
L9 = L-CMLS-ACM2012: Manufacture: 台庆; Part Number: C060402360001; Part Name: 信号共模电感; ID: 1; DSC6: SMD_4P,2x1.2mm; DSC5: -40℃ ~ +125℃; DSC4: DCR=300mΩ; DSC3: 400mA; DSC2: 90Ω@100MHz; DSC1: 90uH@100kHz; ERP Number: 1010200196
L10 = L-CMLS-ACM2012: Part Name: 信号共模电感; Part Number: C060402360001; Manufacture: 台庆; ERP Number: 1010200196; DSC1: 90uH@100kHz; DSC2: 90Ω@100MHz; DSC3: 400mA; DSC4: DCR=300mΩ; DSC5: -40℃ ~ +125℃; DSC6: SMD_4P,2x1.2mm; ID: 1
R68 = R-0402: Part Number: C011002080818; Part Name: 贴片电阻; ID: 818; DSC2: 1/16W; DSC1: ±1%; ERP Number: 1010200445
R69 R313 = R-0402: Part Name: 贴片电阻; Part Number: C011002081059; ERP Number: 1010200459; DSC1: ±1%; DSC2: 1/16W; ID: 1,059
R70 R314 = R-0402: Part Number: C011002080837; Part Name: 贴片电阻; ID: 837; DSC2: 1/16W; DSC1: ±1%; ERP Number: 1010200334
R71 R78-R81 = R-0402: as R56-R58 on sheet P07 SD_RTC
R72 R73 = R-0402: Part Number: C011002080413; Part Name: 贴片电阻; ID: 413; DSC2: 1/16W; DSC1: ±1%
R75 = R-0402: Part Name: 贴片电阻; Part Number: C011002080742; ERP Number: 1010200113; DSC1: ±1%; DSC2: 1/16W; ID: 742
R76 = R-0402: Part Number: C011002080864; Part Name: 贴片电阻; ID: 864; DSC2: 1/16W; DSC1: ±1%; ERP Number: 1010200060
R77 = R-0402: Part Name: 贴片电阻; Part Number: C011002081093; ERP Number: 1010200470; DSC1: ±1%; DSC2: 1/16W; ID: 1,093
R239 = R-0402: as R53 on sheet P06 SOM6ULX
U7 U32 = U-SY6280AAC: Manufacture: 矽力杰; Part Name: 功率开关; Part Number: C070402430001; ID: 1; DSC4: -40~85℃; DSC3: 80m?; DSC2: 2.4-5.5V 2A; DSC1: 低能耗电源开关; ERP Number: 1010100222
U8 = U-USB2514BI-AEZG-TR: Manufacture: MICROCHIP(美国微芯); Part Name: USB芯片; Part Number: C100202500001; ID: 12; DSC3: -40℃~+85℃; DSC2: QFN36，6mm×6mm，0.5mm Pitch; DSC1: USB2.0 HUB 4Ports Industrial; ERP Number: 1010100144
XT2 = XTAL-4P: Manufacture: 泰晶; Part Number: C050102290005; Part Name: 贴片无源晶振; CLASS: IC; ID: 5; DSC5: 3.2*2.5mm 4P; DSC4: -40℃~+85℃; DSC3: 12pF; DSC2: ±10ppm; DSC1: 40Ω

## Sheet P09 ETHERNET.SchDoc
size 594 x 420 mm
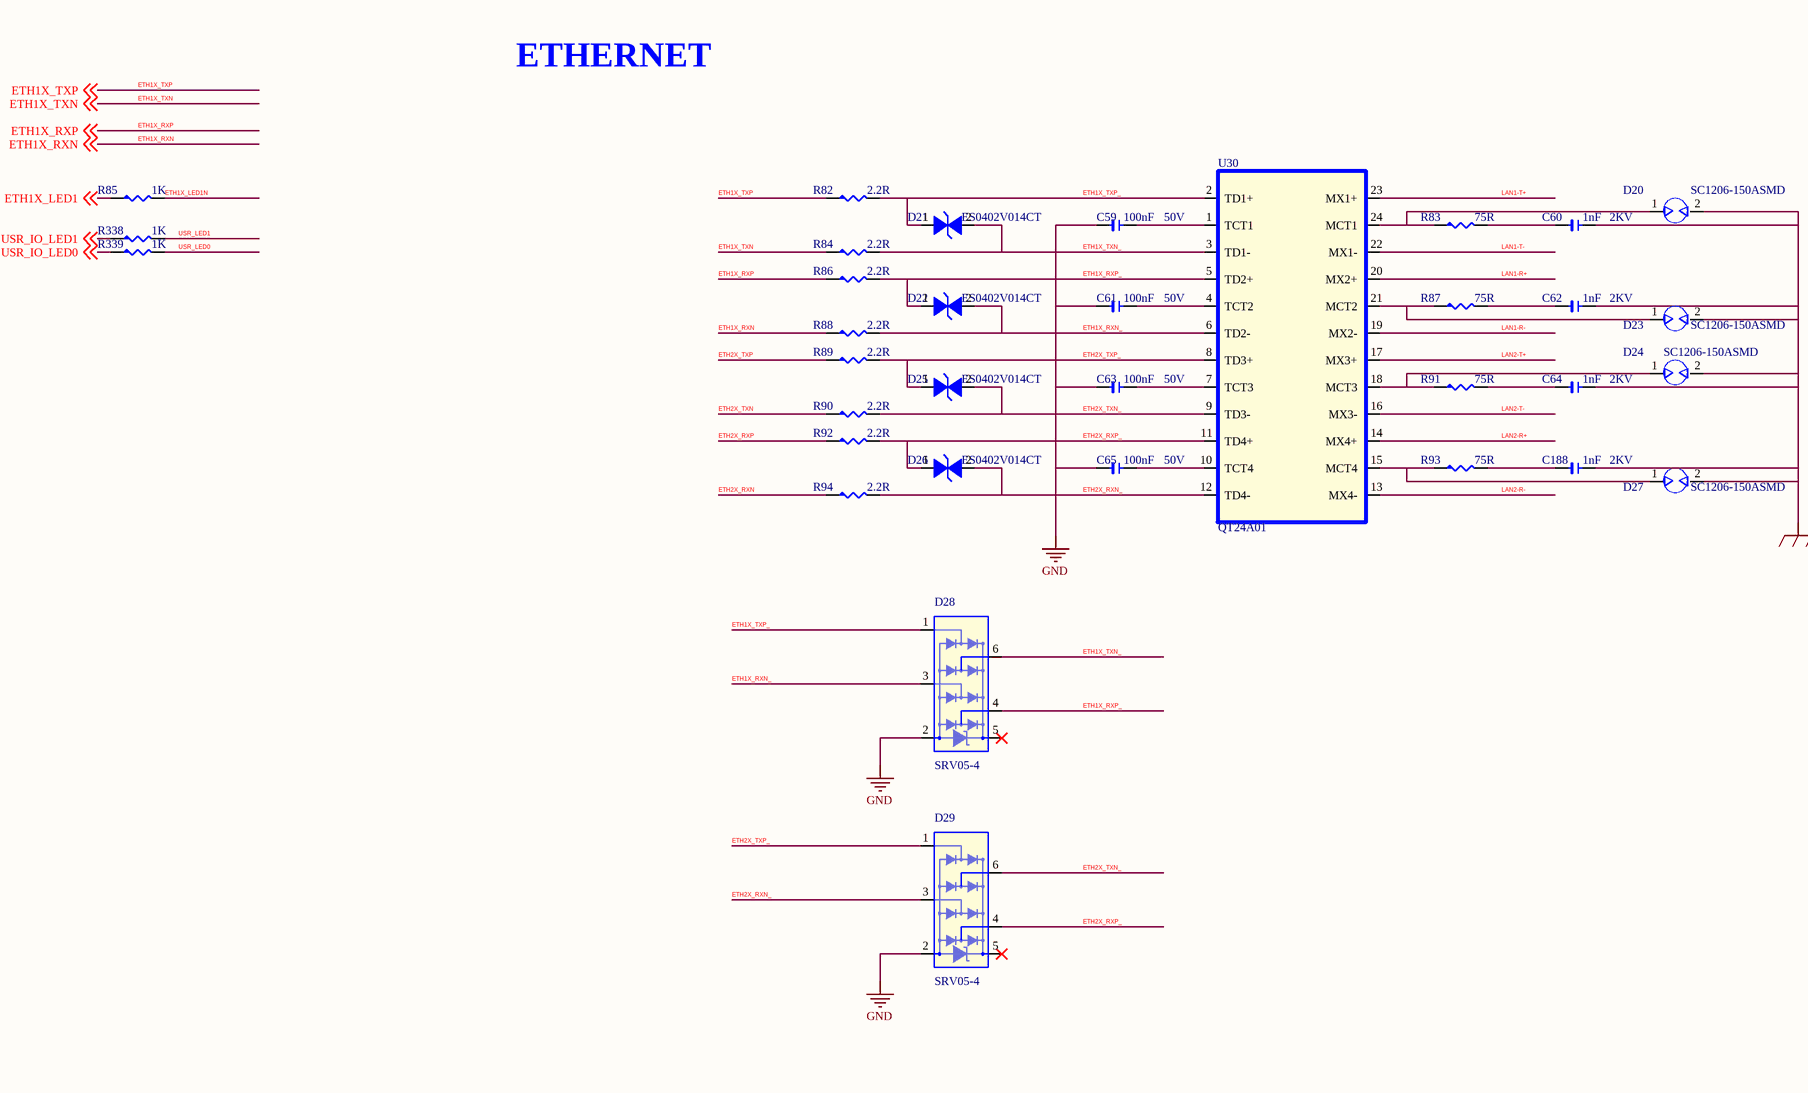
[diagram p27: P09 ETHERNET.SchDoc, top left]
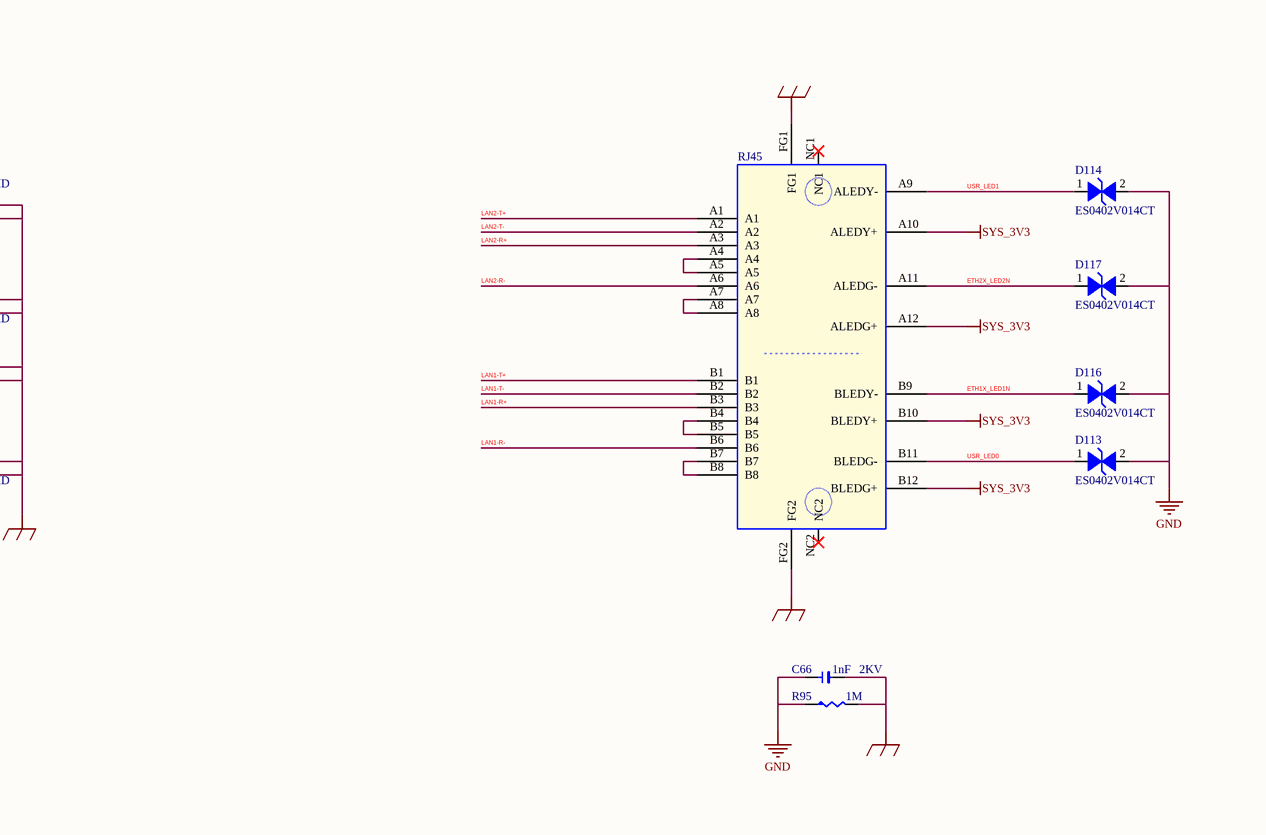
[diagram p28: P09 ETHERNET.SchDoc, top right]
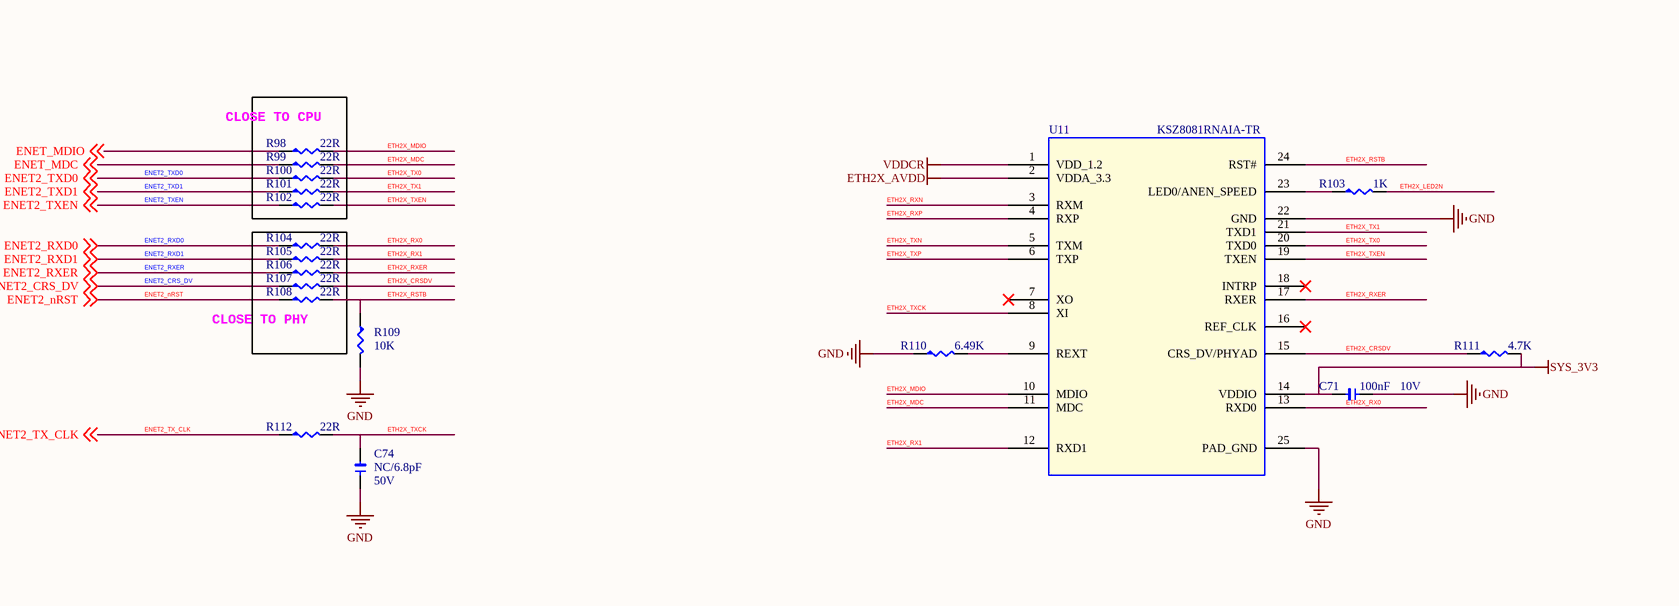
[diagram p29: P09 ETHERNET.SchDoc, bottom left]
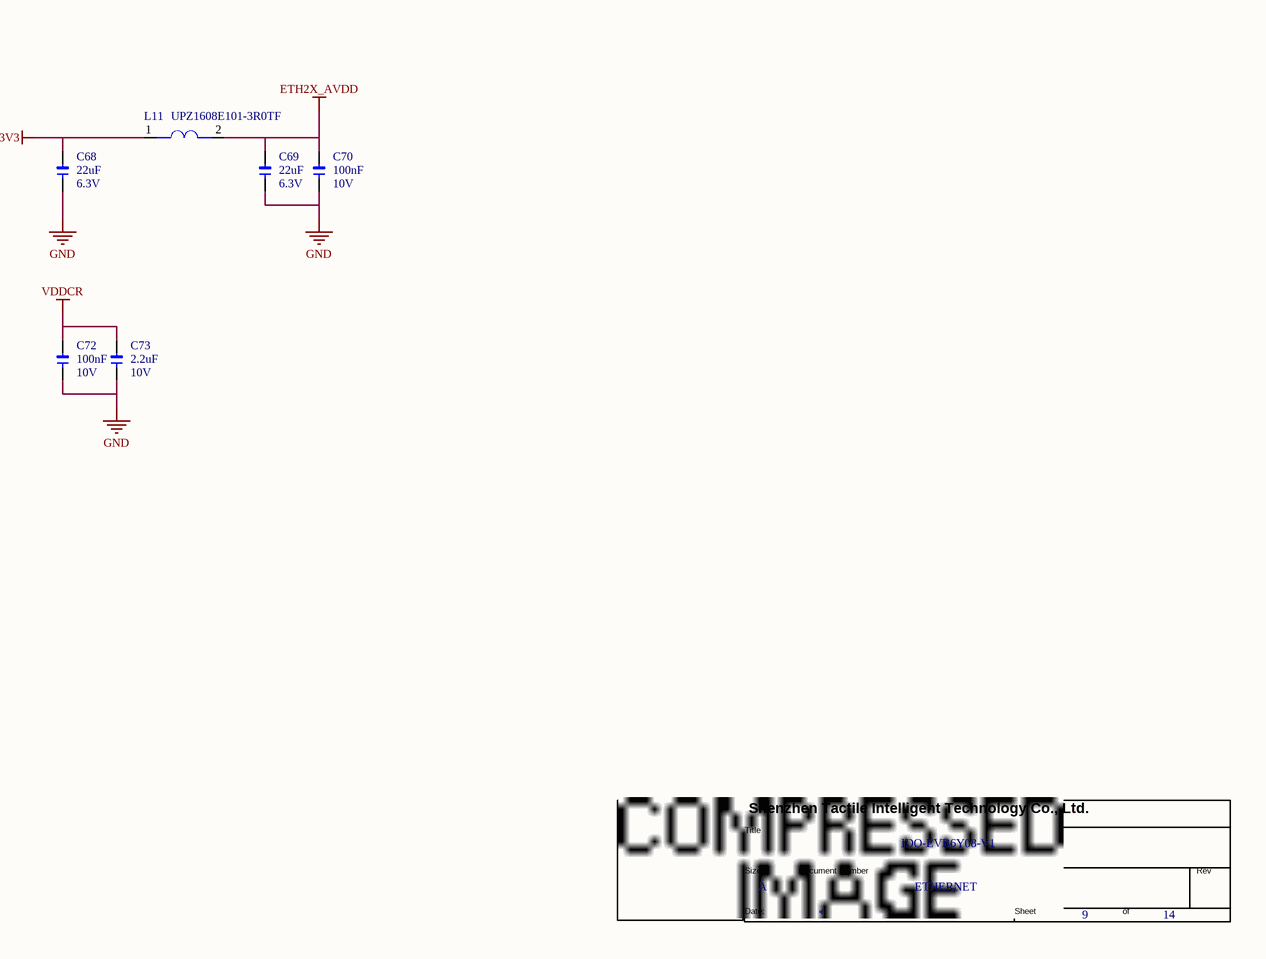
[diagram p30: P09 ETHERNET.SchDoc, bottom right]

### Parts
(Parts that share a designator on the sheet are numbered #1, #2 ... from top to bottom, then left to right.)
*#9  Doc: ETHERNET  Title: IDO-EVB6Y08-V1  Page Size: A  Page Number: 9  Page Count: 14  (hidden comment: TitleBlock1)  (graphical)
C59  100nF  DSC2: 50V  [1206]
C60  1nF  DSC2: 2KV  [1206]
C61  100nF  DSC2: 50V  [1206]
C62  1nF  DSC2: 2KV  [1206]
C63  100nF  DSC2: 50V  [1206]
C64  1nF  DSC2: 2KV  [1206]
C65  100nF  DSC2: 50V  [1206]
C66  1nF  DSC2: 2KV  [1206]
C68  22uF  DSC2: 6.3V  [1206]
C69  22uF  DSC2: 6.3V  [1206]
C70  100nF  DSC2: 10V  [1206]
C71  100nF  DSC2: 10V  [1206]
C72  100nF  DSC2: 10V  [1206]
C73  2.2uF  DSC2: 10V  [1206]
C74  NC/6.8pF  DSC2: 50V  [1206]
C188  1nF  DSC2: 2KV  [1206]
D20  SC1206-150ASMD  [SMD1206]
D21  ES0402V014CT  [V0402]
D22  ES0402V014CT  [V0402]
D23  SC1206-150ASMD  [SMD1206]
D24  SC1206-150ASMD  [SMD1206]
D25  ES0402V014CT  [V0402]
D26  ES0402V014CT  [V0402]
D27  SC1206-150ASMD  [SMD1206]
D28  SRV05-4  [SOT23-6]
D29  SRV05-4  [SOT23-6]
D113  ES0402V014CT  [V0402]
D114  ES0402V014CT  [V0402]
D116  ES0402V014CT  [V0402]
D117  ES0402V014CT  [V0402]
J55  RJ45  [RJ45-1X2-8P8C-R-LED]
L11  UPZ1608E101-3R0TF  [L0603]
R82  2.2R  [R0402L]
R83  75R  [R0603L]
R84  2.2R  [R0402L]
R85  1K  [R0402L]
R86  2.2R  [R0402L]
R87  75R  [R0603L]
R88  2.2R  [R0402L]
R89  2.2R  [R0402L]
R90  2.2R  [R0402L]
R91  75R  [R0603L]
R92  2.2R  [R0402L]
R93  75R  [R0603L]
R94  2.2R  [R0402L]
R95  1M  [R0805L]
R98  22R  [R0402L]
R99  22R  [R0402L]
R100  22R  [R0402L]
R101  22R  [R0402L]
R102  22R  [R0402L]
R103  1K  [R0402L]
R104  22R  [R0402L]
R105  22R  [R0402L]
R106  22R  [R0402L]
R107  22R  [R0402L]
R108  22R  [R0402L]
R109  10K  [R0402L]
R110  6.49K  [R0402L]
R111  4.7K  [R0402L]
R112  22R  [R0402L]
R338  1K  [R0402L]
R339  1K  [R0402L]
U11  KSZ8081RNAIA-TR  [KSZ8081RNAIA-QFN-24]
U30  QT24A01  [QT24A01-SOP24]

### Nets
ETH2X_AVDD: C69.2 C70.2 L11.2 U11.2(VDDA_3.3)
GND: C59.2 C61.2 C63.2 C65.2 C66.1 C68.1 C69.1 C70.1 C71.1 C72.1 C73.1 C74.1 D28.2 D29.2 D113.2(I/O1) D114.2(I/O1) D116.2(I/O1) D117.2(I/O1) R95.1 R109.2 R110.1 U11.22(GND) U11.25(PAD_GND)
GND_EARTH: C60.1 C62.1 C64.1 C66.2 C188.1 D20.2 D23.2 D24.2 D27.2 J55.FG1 J55.FG2 R95.2
SYS_3V3: C68.2 C71.2 J55.A10(ALEDY+) J55.A12(ALEDG+) J55.B10(BLEDY+) J55.B12(BLEDG+) L11.1 R111.2 U11.14(VDDIO)
VDDCR: C72.2 C73.2 U11.1(VDD_1.2)
ENET2_CRS_DV: R107.1 ; off-sheet ENET2_CRS_DV
ENET2_nRST: R108.1 ; off-sheet ENET2_nRST
ENET2_RXD0: R104.1 ; off-sheet ENET2_RXD0
ENET2_RXD1: R105.1 ; off-sheet ENET2_RXD1
ENET2_RXER: R106.1 ; off-sheet ENET2_RXER
ENET2_TX_CLK: R112.1 ; off-sheet ENET2_TX_CLK
ENET2_TXD0: R100.1 ; off-sheet ENET2_TXD0
ENET2_TXD1: R101.1 ; off-sheet ENET2_TXD1
ENET2_TXEN: R102.1 ; off-sheet ENET2_TXEN
ENET_MDC: R99.1 ; off-sheet ENET_MDC
ENET_MDIO: R98.1 ; off-sheet ENET_MDIO
ETH1X_LED1: R85.1 ; off-sheet ETH1X_LED1
ETH1X_LED1N: D116.1(I/O2) J55.B9(BLEDY-) R85.2
ETH1X_RXN: R88.1 ; off-sheet ETH1X_RXN
ETH1X_RXN_: D22.2(I/O1) D28.3 R88.2 U30.6(TD2-)
ETH1X_RXP: R86.1 ; off-sheet ETH1X_RXP
ETH1X_RXP_: D22.1(I/O2) D28.4 R86.2 U30.5(TD2+)
ETH1X_TXN: R84.1 ; off-sheet ETH1X_TXN
ETH1X_TXN_: D21.2(I/O1) D28.6 R84.2 U30.3(TD1-)
ETH1X_TXP: R82.1 ; off-sheet ETH1X_TXP
ETH1X_TXP_: D21.1(I/O2) D28.1 R82.2 U30.2(TD1+)
ETH2X_CRSDV: R107.2 R111.1 U11.15(CRS_DV/PHYAD)
ETH2X_LED2N: D117.1(I/O2) J55.A11(ALEDG-) R103.2
ETH2X_MDC: R99.2 U11.11(MDC)
ETH2X_MDIO: R98.2 U11.10(MDIO)
ETH2X_RSTB: R108.2 R109.1 U11.24(RST#)
ETH2X_RX0: R104.2 U11.13(RXD0)
ETH2X_RX1: R105.2 U11.12(RXD1)
ETH2X_RXER: R106.2 U11.17(RXER)
ETH2X_RXN: R94.1 U11.3(RXM)
ETH2X_RXN_: D26.2(I/O1) D29.3 R94.2 U30.12(TD4-)
ETH2X_RXP: R92.1 U11.4(RXP)
ETH2X_RXP_: D26.1(I/O2) D29.4 R92.2 U30.11(TD4+)
ETH2X_TX0: R100.2 U11.20(TXD0)
ETH2X_TX1: R101.2 U11.21(TXD1)
ETH2X_TXCK: C74.2 R112.2 U11.8(XI)
ETH2X_TXEN: R102.2 U11.19(TXEN)
ETH2X_TXN: R90.1 U11.5(TXM)
ETH2X_TXN_: D25.2(I/O1) D29.6 R90.2 U30.9(TD3-)
ETH2X_TXP: R89.1 U11.6(TXP)
ETH2X_TXP_: D25.1(I/O2) D29.1 R89.2 U30.8(TD3+)
LAN1-R+: J55.B3 U30.20(MX2+)
LAN1-R-: J55.B6 U30.19(MX2-)
LAN1-T+: J55.B1 U30.23(MX1+)
LAN1-T-: J55.B2 U30.22(MX1-)
LAN2-R+: J55.A3 U30.14(MX4+)
LAN2-R-: J55.A6 U30.13(MX4-)
LAN2-T+: J55.A1 U30.17(MX3+)
LAN2-T-: J55.A2 U30.16(MX3-)
USR_IO_LED0: R339.1 ; off-sheet USR_IO_LED0  [project net SNVS_TAMPER3]
USR_IO_LED1: R338.1 ; off-sheet USR_IO_LED1  [project net SNVS_TAMPER4]
USR_LED0: D113.1(I/O2) J55.B11(BLEDG-) R339.2
USR_LED1: D114.1(I/O2) J55.A9(ALEDY-) R338.2
NetC59_1: C59.1 U30.1(TCT1)
NetC60_2: C60.2 R83.2
NetC61_1: C61.1 U30.4(TCT2)
NetC62_2: C62.2 R87.2
NetC63_1: C63.1 U30.7(TCT3)
NetC64_2: C64.2 R91.2
NetC65_1: C65.1 U30.10(TCT4)
NetC188_2: C188.2 R93.2
NetD20_1: D20.1 R83.1 U30.24(MCT1)
NetD23_1: D23.1 R87.1 U30.21(MCT2)
NetD24_1: D24.1 R91.1 U30.18(MCT3)
NetD27_1: D27.1 R93.1 U30.15(MCT4)
NetJ55_A4: J55.A4 J55.A5
NetJ55_A7: J55.A7 J55.A8
NetJ55_B4: J55.B4 J55.B5
NetJ55_B7: J55.B7 J55.B8
NetR103_1: R103.1 U11.23(LED0/ANEN_SPEED)
NetR110_2: R110.2 U11.9(REXT)

Not connected (* = marked no-connect by the designer): D28 5*; D29 5*; J55 NC1* NC2*; U11 7(XO)* 16(REF_CLK)* 18(INTRP)*

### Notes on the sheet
- ETHERNET
- CLOSE TO CPU
- (near R108) CLOSE TO PHY

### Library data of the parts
C59 C63 C65 = C-0402: Part Number: C020102120061; Part Name: 贴片电容; Manufacture: 三星¦国巨¦村田; PCB Footprint: C0402L; ERP Number: 1010200128; DSC1: ±10%; DSC3: X7R; ID: 61
C60 C188 = C-1206: Part Number: C020102120077; Part Name: 贴片电容; Manufacture: 三星¦国巨¦村田; PCB Footprint: C1206L; ERP Number: 1010200094; DSC1: ±10%; DSC3: X7R; ID: 77
C61 = C-0402: Manufacture: 三星¦国巨¦村田; Part Name: 贴片电容; Part Number: C020102120061; PCB Footprint: C0402L; ID: 61; DSC3: X7R; DSC1: ±10%; ERP Number: 1010200128
C62 C64 = C-1206: Manufacture: 三星¦国巨¦村田; Part Name: 贴片电容; Part Number: C020102120077; PCB Footprint: C1206L; ID: 77; DSC3: X7R; DSC1: ±10%; ERP Number: 1010200094
C66 = C-1206: Manufacture: 三星¦国巨¦村田; Part Name: 贴片电容; Part Number: C020102120077; ID: 77; DSC3: X7R; DSC1: ±10%; ERP Number: 1010200094; PCB Footprint: C1206L
C68 = C-0603: Part Number: C020102120072; Part Name: 贴片电容; Manufacture: 三星¦国巨¦村田; ERP Number: 1010200133; DSC1: ±20%; DSC3: X5R; ID: 72; PCB Footprint: C0603L
C69 = C-0603: as C36 on sheet P06 SOM6ULX
C70 = C-0402: Part Number: C020102120060; Part Name: 贴片电容; Manufacture: 三星¦国巨¦村田; DSC1: ±10%; DSC3: X7R; ID: 60; PCB Footprint: C0402L
C71 C72 = C-0402: Manufacture: 三星¦国巨¦村田; Part Name: 贴片电容; Part Number: C020102120060; ID: 60; DSC3: X7R; DSC1: ±10%; PCB Footprint: C0402L
C73 = C-0402: Manufacture: 三星¦国巨¦村田; Part Name: 贴片电容; Part Number: C020102120066; ID: 66; DSC3: X5R; DSC1: ±10%; PCB Footprint: C0402L
C74 = C-0402: Part Number: C020102120018; Part Name: 贴片电容; Manufacture: 三星¦国巨¦村田; ERP Number: 1010200056; DSC1: ±0.25PF; DSC3: C0G; ID: 18; PCB Footprint: C0402L
D20 D24 = DI-SC1206-150ASMD: Manufacture: 硕凯; Part Number: C040702270002; Part Name: 放电管; ID: 2; DSC4: SMD,3.2x1.6mm; DSC3: 500A; DSC2: ±30%; DSC1: 150V
D21 D26 D113 D114 D116 D117 = DI-ESD: as D96 on sheet P06 SOM6ULX
D22 D25 = DI-ESD: as D8-D12 on sheet P07 SD_RTC
D23 D27 = DI-SC1206-150ASMD: Part Name: 放电管; Part Number: C040702270002; Manufacture: 硕凯; DSC1: 150V; DSC2: ±30%; DSC3: 500A; DSC4: SMD,3.2x1.6mm; ID: 2
D28 D29 = DI-ESD-SRV05-4: Part Number: C040602260015; Part Name: TVS; Manufacture: 伯恩半导体; ERP Number: 1010800050; DSC1: 单向; DSC2: Vrwm=5V; DSC3: VBR=6V; DSC4: Vc=13V; DSC5: Ipp=3.5A; DSC6: Ppp=45W; DSC7: Cj=0.36pF; ID: 15; Solder: 量产
J55 = J-RJ45-1X2: Part Number: J120103060002; ID: 2; DSC3: 通孔弯针; DSC1: RJ45网口连接器,带LED灯,8p8c,横向并排双座,黑色,后脚,4.57,铜壳,无弹片
L11 = FB-0603: as L5 on sheet P06 SOM6ULX
R82 R89 = R-0402: Part Name: 贴片电阻; Part Number: C011002080453; DSC1: ±1%; DSC2: 1/16W; ID: 453
R83 R87 R91 R93 = R-0603: Part Name: 贴片电阻; Part Number: C011002081348; ERP Number: 1010200269; DSC1: ±1%; DSC2: 1/10W; ID: 1,348
R84 R86 R88 R90 R92 R94 = R-0402: Part Number: C011002080453; Part Name: 贴片电阻; ID: 453; DSC2: 1/16W; DSC1: ±1%
R85 = R-0402: as R75 on sheet P08 USB
R95 = R-0805: Part Number: C011002081864; Part Name: 贴片电阻; ID: 1,864; DSC2: 1/8W; DSC1: ±1%; ERP Number: 1010200447
R98 R99 R102 R108 = R-0402: as R32-R37 on sheet P06 SOM6ULX
R100 R101 R104-R107 R112 = R-0402: as R38 on sheet P06 SOM6ULX
R103 R338 R339 = R-0402: Part Number: C011002080742; Part Name: 贴片电阻; ID: 742; DSC2: 1/16W; DSC1: ±1%; ERP Number: 1010200113
R109 = R-0402: as R56-R58 on sheet P07 SD_RTC
R110 = R-0402: Part Number: C011002080835; Part Name: 贴片电阻; ID: 835; DSC2: 1/16W; DSC1: ±1%; ERP Number: 1010200185
R111 = R-0402: as R68 on sheet P08 USB
U11 = U-KSZ8081RNAIA-TR: Part Number: C100102490003; Part Name: 以太网芯片; Manufacture: MICROCHIP(美国微芯); CLASS: IC; ERP Number: 1010100248; DSC1: 10BASE-T/100BASE-TX Physical Layer ?Transceiver, RMII,IEEE 802.3; DSC2: QFN24，4mm×4mm，0.5mm Pitch; DSC3: -40℃~+85℃; ID: 3
U30 = U-QT24A01_0: Part Name: 网口变压器; ID: 2; ERP Number: C060702390002; DSC1: 贴片 单口千兆或双口百兆; DSC2: 0~70℃; DSC3: SMD,SOP24,15.1*7*4mm

## Sheet P10 UART_Debug.SchDoc
size 594 x 420 mm
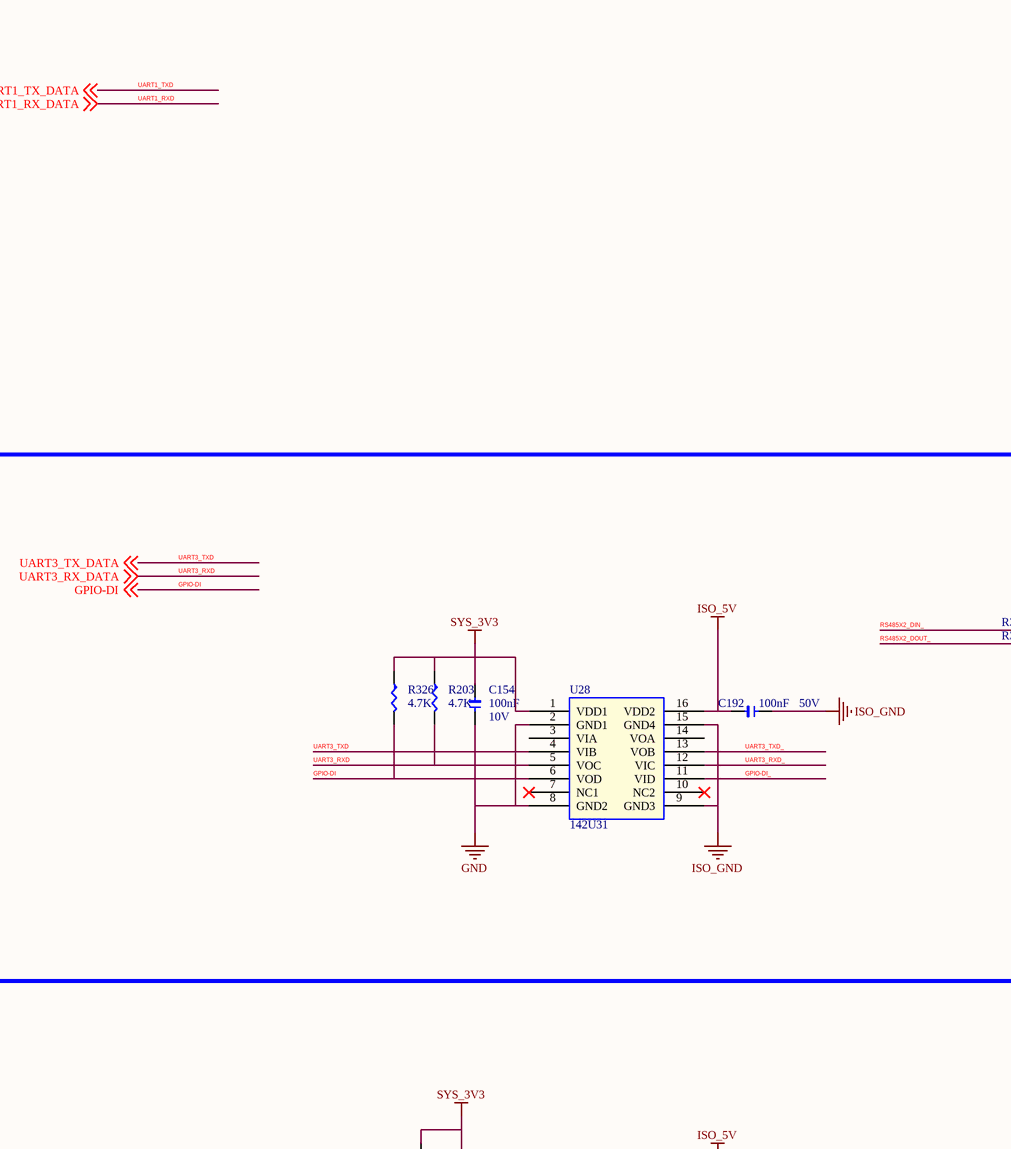
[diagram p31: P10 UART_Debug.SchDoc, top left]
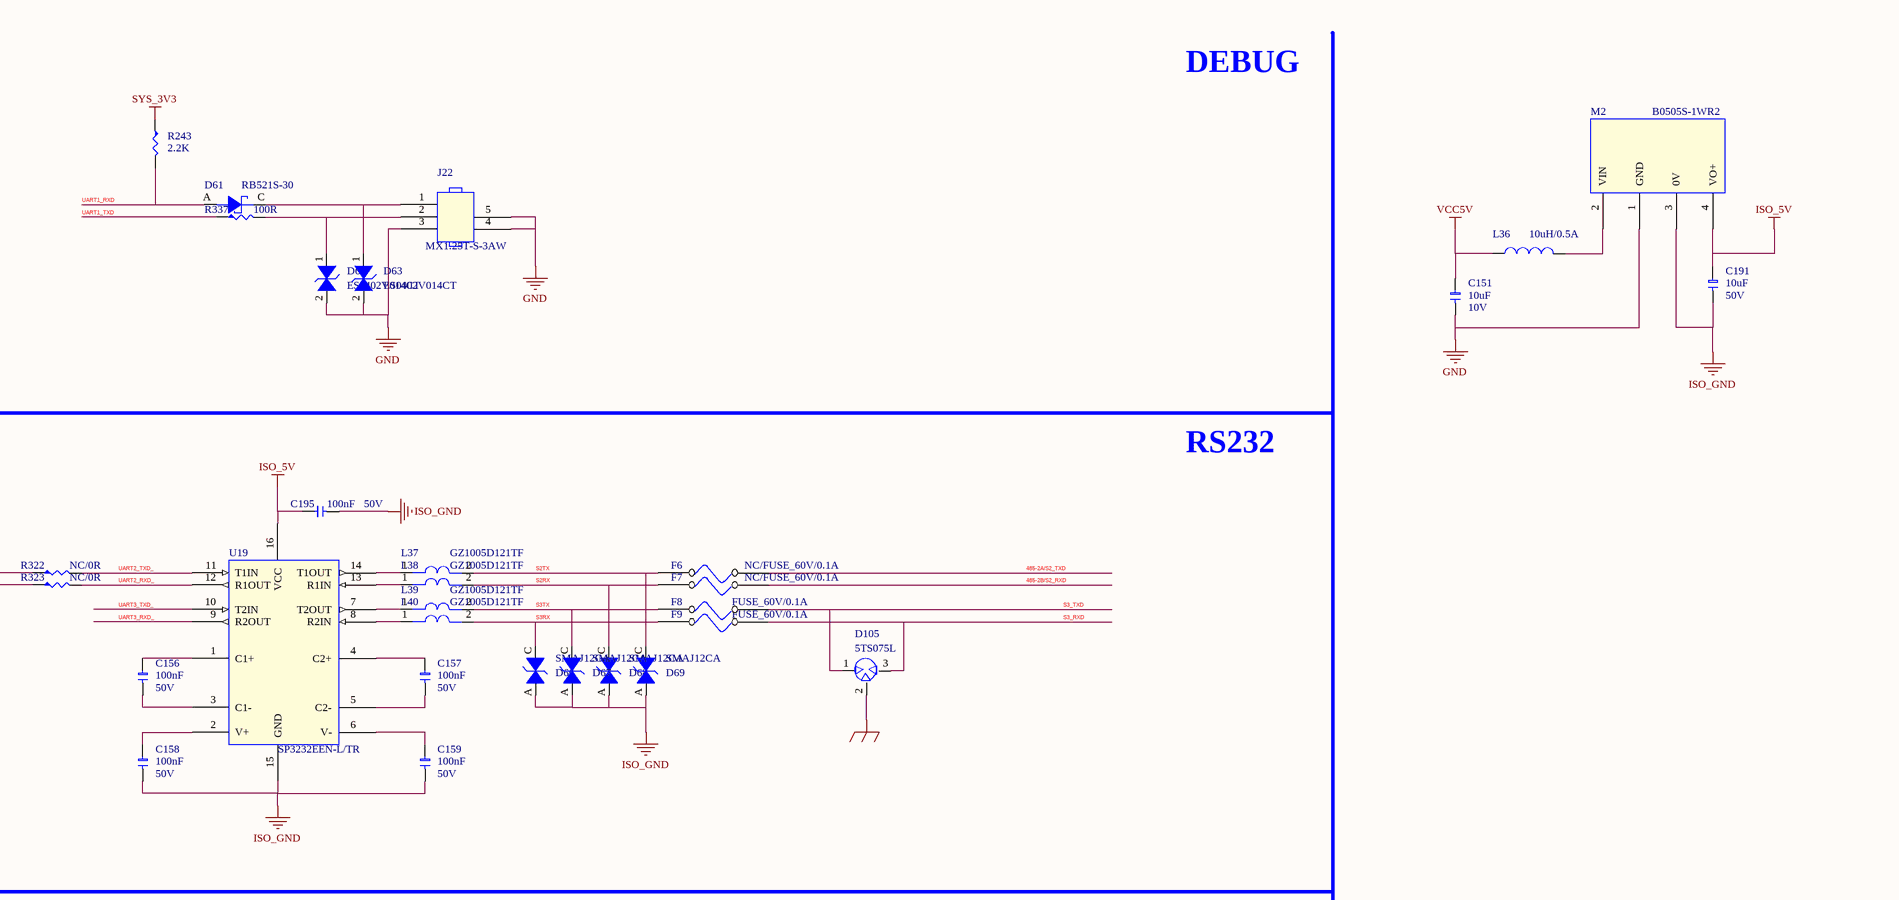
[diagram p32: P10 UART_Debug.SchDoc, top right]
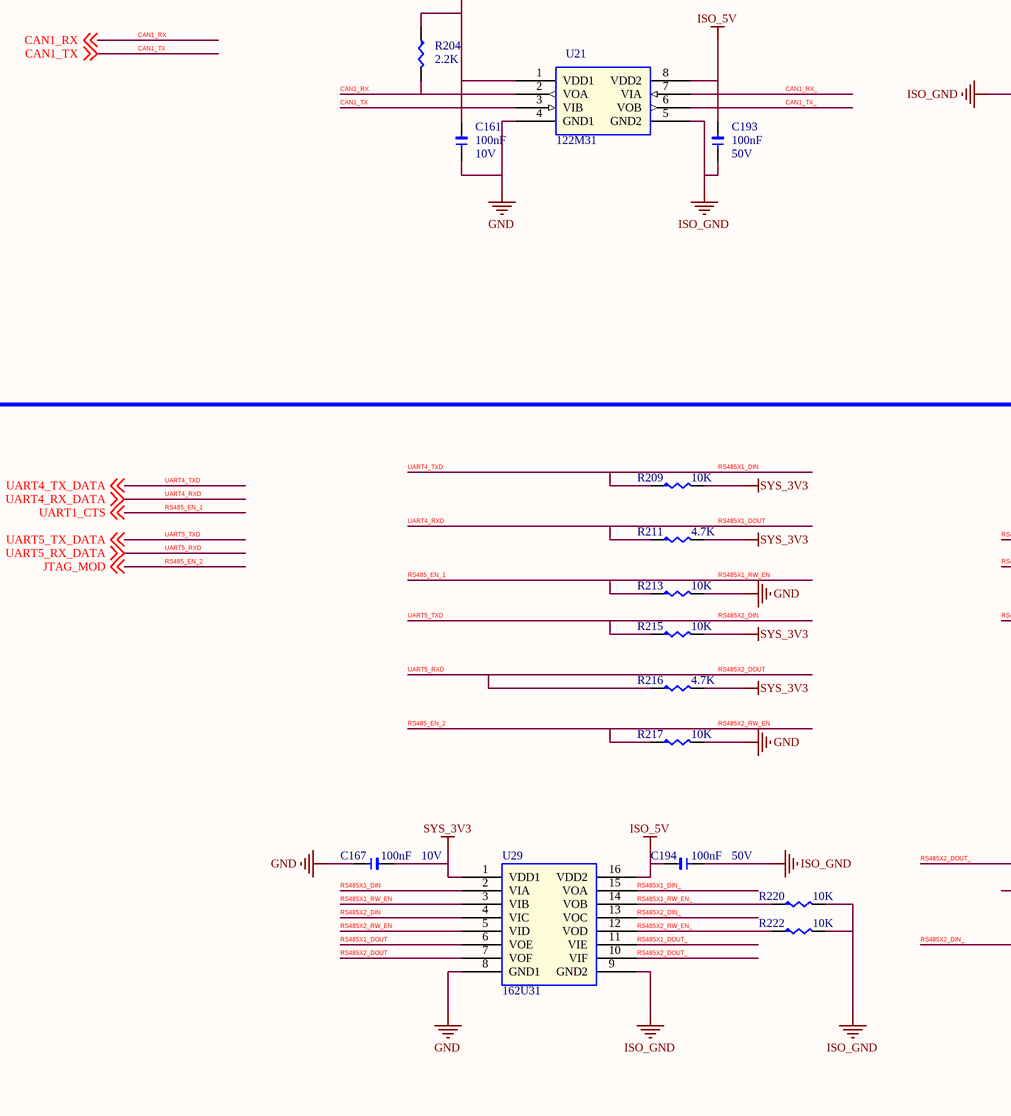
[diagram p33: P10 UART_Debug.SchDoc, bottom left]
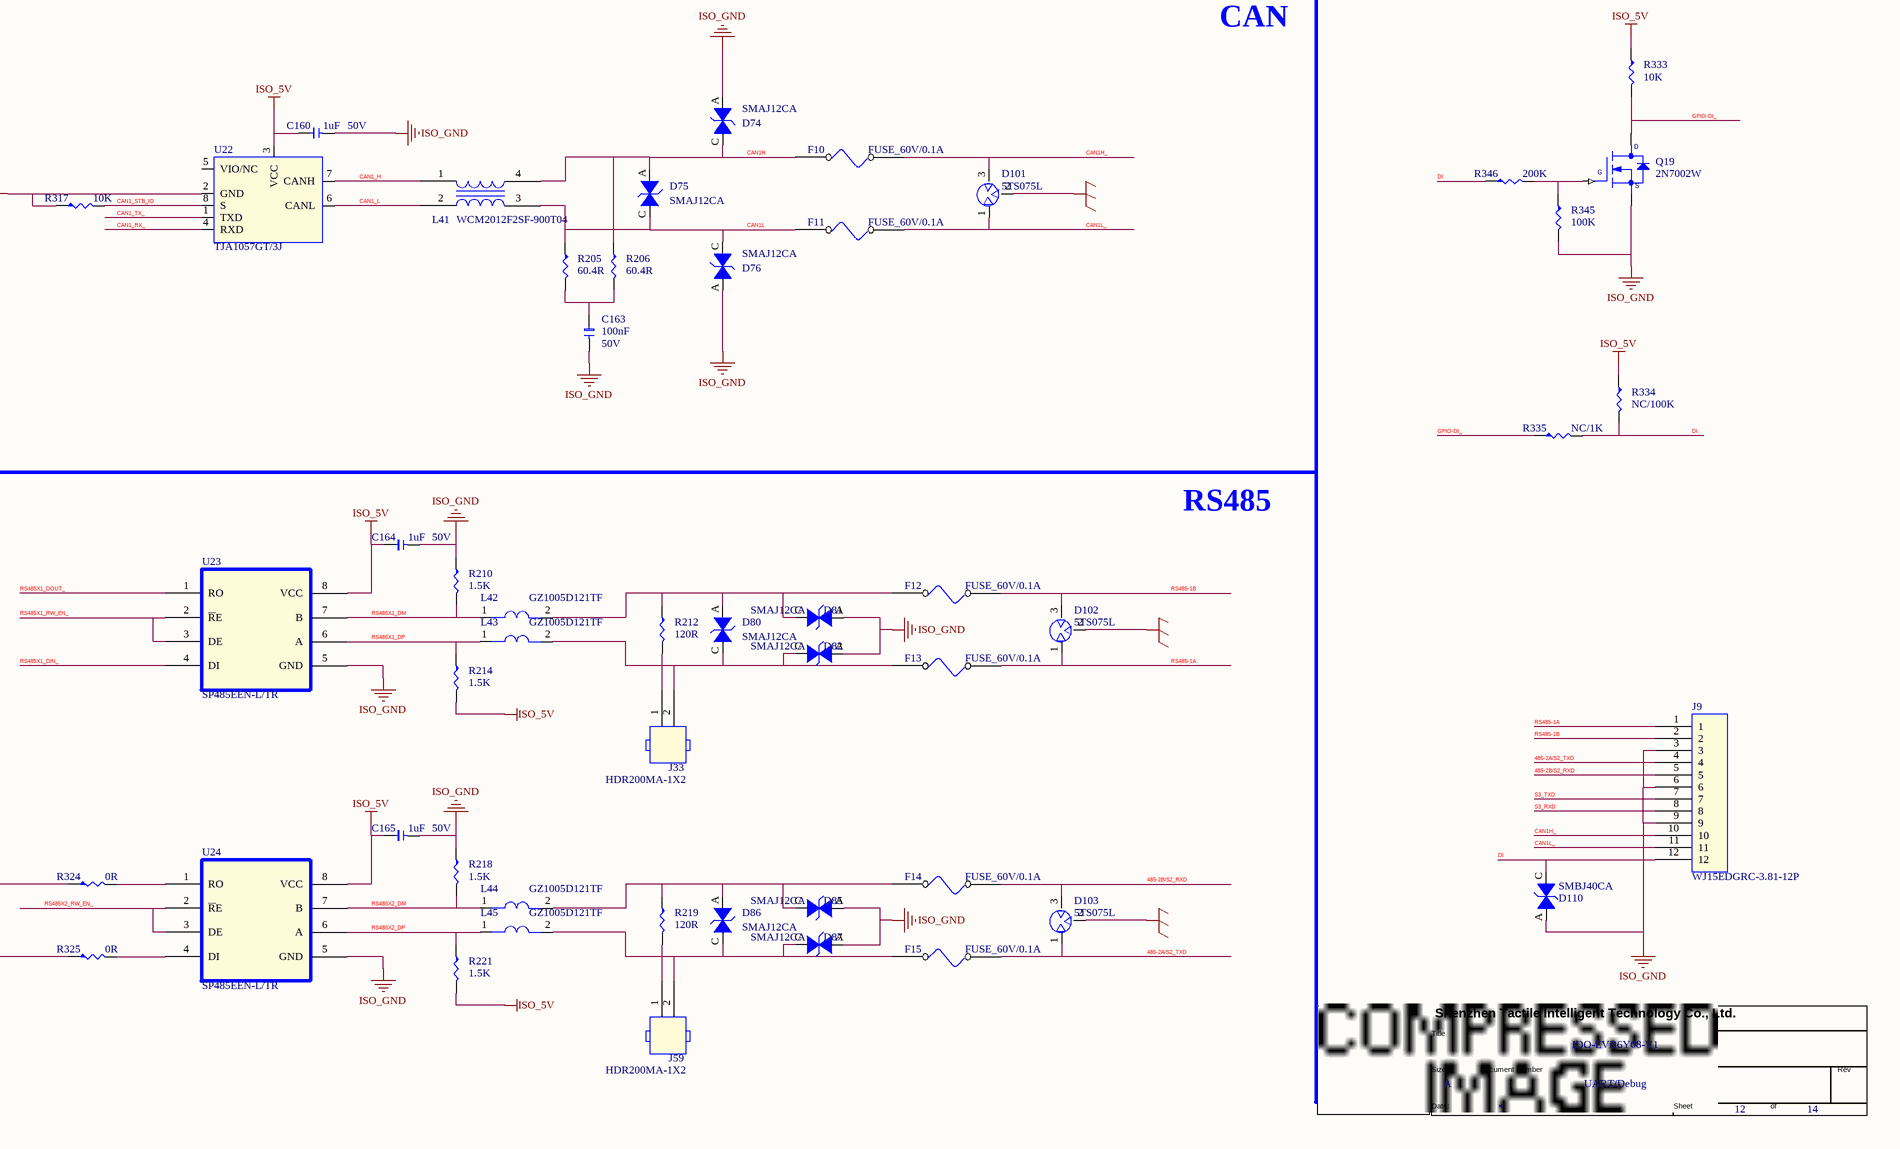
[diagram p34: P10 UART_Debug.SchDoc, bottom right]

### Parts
(Parts that share a designator on the sheet are numbered #1, #2 ... from top to bottom, then left to right.)
*#10  Doc: UART/Debug  Title: IDO-EVB6Y08-V1  Page Size: A  Page Number: 12  Page Count: 14  (hidden comment: TitleBlock1)  (graphical)
C151  10uF  DSC2: 10V  [1206]
C154  100nF  DSC2: 10V  [1206]
C156  100nF  DSC2: 50V  [1206]
C157  100nF  DSC2: 50V  [1206]
C158  100nF  DSC2: 50V  [1206]
C159  100nF  DSC2: 50V  [1206]
C160  1uF  DSC2: 50V  [1206]
C161  100nF  DSC2: 10V  [1206]
C163  100nF  DSC2: 50V  [1206]
C164  1uF  DSC2: 50V  [1206]
C165  1uF  DSC2: 50V  [1206]
C167  100nF  DSC2: 10V  [1206]
C191  10uF  DSC2: 50V  [1206]
C192  100nF  DSC2: 50V  [1206]
C193  100nF  DSC2: 50V  [1206]
C194  100nF  DSC2: 50V  [1206]
C195  100nF  DSC2: 50V  [1206]
D61  RB521S-30  [SOD523]
D62  ES0402V014CT  [V0402]
D63  ES0402V014CT  [V0402]
D66  SMAJ12CA  [SMA_DO-214AC]
D67  SMAJ12CA  [SMA_DO-214AC]
D68  SMAJ12CA  [SMA_DO-214AC]
D69  SMAJ12CA  [SMA_DO-214AC]
D74  SMAJ12CA  [SMA_DO-214AC]
D75  SMAJ12CA  [SMA_DO-214AC]
D76  SMAJ12CA  [SMA_DO-214AC]
D80  SMAJ12CA  [SMA_DO-214AC]
D81  SMAJ12CA  [SMA_DO-214AC]
D82  SMAJ12CA  [SMA_DO-214AC]
D85  SMAJ12CA  [SMA_DO-214AC]
D86  SMAJ12CA  [SMA_DO-214AC]
D87  SMAJ12CA  [SMA_DO-214AC]
D101  5TS075L  [SMD-GDT-3RM-50X75]
D102  5TS075L  [SMD-GDT-3RM-50X75]
D103  5TS075L  [SMD-GDT-3RM-50X75]
D105  5TS075L  [SMD-GDT-3RM-50X75]
D110  SMBJ40CA  [SMB_DO-214AA]
F6  NC/FUSE_60V/0.1A  [SMD1206]
F7  NC/FUSE_60V/0.1A  [SMD1206]
F8  FUSE_60V/0.1A  [SMD1206]
F9  FUSE_60V/0.1A  [SMD1206]
F10  FUSE_60V/0.1A  [SMD1206]
F11  FUSE_60V/0.1A  [SMD1206]
F12  FUSE_60V/0.1A  [SMD1206]
F13  FUSE_60V/0.1A  [SMD1206]
F14  FUSE_60V/0.1A  [SMD1206]
F15  FUSE_60V/0.1A  [SMD1206]
J9  WJ15EDGRC-3.81-12P  [WJ15EDGR-381T-12P]
J22  MX1.25T-S-3AW  [MX125T-S-3AW]
J33  HDR200MA-1X2  [HDR200MA-1X2]
J59  HDR200MA-1X2  [HDR200MA-1X2]
L36  10uH/0.5A  [L2520]
L37  GZ1005D121TF  [L0402]
L38  GZ1005D121TF  [L0402]
L39  GZ1005D121TF  [L0402]
L40  GZ1005D121TF  [L0402]
L41  WCM2012F2SF-900T04  [CMLS-ACM2012]
L42  GZ1005D121TF  [L0402]
L43  GZ1005D121TF  [L0402]
L44  GZ1005D121TF  [L0402]
L45  GZ1005D121TF  [L0402]
M2  B0505S-1WR2  [B0505S-1WR2-SIP4]
Q19  2N7002W  [SOT323]
R203  4.7K  [R0402L]
R204  2.2K  [R0402L]
R205  60.4R  [R0603L]
R206  60.4R  [R0603L]
R209  10K  [R0402L]
R210  1.5K  [R0603L]
R211  4.7K  [R0402L]
R212  120R  [R1206L]
R213  10K  [R0402L]
R214  1.5K  [R0603L]
R215  10K  [R0402L]
R216  4.7K  [R0402L]
R217  10K  [R0402L]
R218  1.5K  [R0603L]
R219  120R  [R1206L]
R220  10K  [R0402L]
R221  1.5K  [R0603L]
R222  10K  [R0402L]
R243  2.2K  [R0402L]
R317  10K  [R0402L]
R322  NC/0R  [R0402L]
R323  NC/0R  [R0402L]
R324  0R  [R0402L]
R325  0R  [R0402L]
R326  4.7K  [R0402L]
R333  10K  [R0402L]
R334  NC/100K  [R0402L]
R335  NC/1K  [R0402L]
R337  100R  [R0402L]
R345  100K  [R0402L]
R346  200K  [R0402L]
U19  SP3232EEN-L/TR  [SP3232EEN-SOP16]
U21  122M31  [SOP8-P127-390X490]
U22  TJA1057GT/3J  [SOP8-P127-390X490]
U23  SP485EEN-L/TR  [SOP8-P127-390X490]
U24  SP485EEN-L/TR  [SOP8-P127-390X490]
U28  142U31  [142U31-SOP16]
U29  162U31  [162U31-SOP16]

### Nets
GND: C151.1 C154.1 C161.1 C167.1 D62.2(I/O1) D63.2(I/O1) J22.3 J22.4 J22.5 M2.1(GND) R213.2 R217.2 U21.4(GND1) U28.2(GND1) U28.8(GND2) U29.8(GND1)
GND_EARTH: D101.2 D102.2 D103.2 D105.2
ISO_5V: C160.2 C164.2 C165.2 C191.2 C192.2 C193.2 C194.2 C195.2 M2.4(VO+) R214.2 R221.2 R333.1 R334.1 U19.16(VCC) U21.8(VDD2) U22.3(VCC) U23.8(VCC) U24.8(VCC) U28.16(VDD2) U29.16(VDD2)
ISO_GND: C158.1 C159.1 C160.1 C163.1 C164.1 C165.1 C191.1 C192.1 C193.1 C194.1 C195.1 D66.A(I/O2) D67.A(I/O2) D68.A(I/O2) D69.A(I/O2) D74.A(I/O2) D76.A(I/O2) D81.A(I/O2) D82.A(I/O2) D85.A(I/O2) D87.A(I/O2) D110.A(I/O2) J9.3 J9.6 J9.9 M2.3(0V) Q19.2(SOURCE) R210.1 R218.1 R220.2 R222.2 R317.1 R345.2 U19.15(GND) U21.5(GND2) U22.2(GND) U23.5(GND) U24.5(GND) U28.9(GND3) U28.15(GND4) U29.9(GND2)
SYS_3V3: C154.2 C161.2 C167.2 R203.1 R204.1 R209.2 R211.2 R215.2 R216.2 R243.1 R326.1 U21.1(VDD1) U28.1(VDD1) U29.1(VDD1)
VCC5V: C151.2 L36.1
485-2A/S2_TXD: D103.1 F6.2 F15.2 J9.4
485-2B/S2_RXD: D103.3 F7.2 F14.2 J9.5
CAN1_H: L41.1 U22.7(CANH)
CAN1_L: L41.2 U22.6(CANL)
CAN1_RX: R204.2 U21.2(VOA) ; off-sheet CAN1_RX
CAN1_RX_: U21.7(VIA) U22.4(RXD)
CAN1_STB_IO: R317.2 U22.8(S)
CAN1_TX: U21.3(VIB) ; off-sheet CAN1_TX
CAN1_TX_: U21.6(VOB) U22.1(TXD)
CAN1H: D74.C(I/O1) D75.A(I/O2) F10.1 L41.4 R206.1
CAN1H_: D101.3 F10.2 J9.10
CAN1L: D75.C(I/O1) D76.C(I/O1) F11.1 L41.3 R205.1
CAN1L_: D101.1 F11.2 J9.11
DI: D110.C(I/O1) J9.12 R334.2 R335.2 R346.1
GPIO-DI: R326.2 U28.6(VOD) ; off-sheet GPIO-DI
GPIO-DI_: Q19.3(DRAIN) R333.2 R335.1 U28.11(VID)
JTAG_MOD: R217.1 U29.5(VID) ; off-sheet JTAG_MOD  [also labelled RS485_EN_2, RS485X2_RW_EN]
RS485-1A: D102.1 F13.2 J9.1
RS485-1B: D102.3 F12.2 J9.2
RS485_EN_1: R213.1 U29.3(VIB) ; off-sheet UART1_CTS  [also labelled RS485X1_RW_EN, UART1_CTS]
RS485X1_DIN: R209.1 U29.2(VIA) ; off-sheet UART4_TX_DATA  [also labelled UART4_TX_DATA, UART4_TXD]
RS485X1_DIN_: U23.4(DI) U29.15(VOA)
RS485X1_DM: L42.1 R210.2 U23.7(B)
RS485X1_DOUT: R211.1 U29.6(VOE) ; off-sheet UART4_RX_DATA  [also labelled UART4_RX_DATA, UART4_RXD]
RS485X1_DOUT_: U23.1(RO) U29.11(VIE)
RS485X1_DP: L43.1 R214.1 U23.6(A)
RS485X1_RW_EN_: R220.1 U23.2(~{R}E) U23.3(DE) U29.14(VOB)
RS485X2_DIN: R215.1 U29.4(VIC) ; off-sheet UART5_TX_DATA  [also labelled UART5_TX_DATA, UART5_TXD]
RS485X2_DIN_: R322.1 R325.1 U29.13(VOC)
RS485X2_DM: L44.1 R218.2 U24.7(B)
RS485X2_DOUT: R216.1 U29.7(VOF) ; off-sheet UART5_RX_DATA  [also labelled UART5_RX_DATA, UART5_RXD]
RS485X2_DOUT_: R323.1 R324.1 U29.10(VIF)
RS485X2_DP: L45.1 R221.1 U24.6(A)
RS485X2_RW_EN_: R222.1 U24.2(~{R}E) U24.3(DE) U29.12(VOD)
S2RX: D68.C(I/O1) F7.1 L38.2
S2TX: D69.C(I/O1) F6.1 L37.2
S3_RXD: D105.3 F9.2 J9.8
S3_TXD: D105.1 F8.2 J9.7
S3RX: D66.C(I/O1) F9.1 L40.2
S3TX: D67.C(I/O1) F8.1 L39.2
UART1_RX_DATA: D61.A R243.2 ; off-sheet UART1_RX_DATA  [also labelled UART1_RXD]
UART1_TX_DATA: R337.1 ; off-sheet UART1_TX_DATA  [also labelled UART1_TXD]
UART2_RXD_: R323.2 U19.12(R1OUT)
UART2_TXD_: R322.2 U19.11(T1IN)
UART3_RX_DATA: R203.2 U28.5(VOC) ; off-sheet UART3_RX_DATA  [also labelled UART3_RXD]
UART3_RXD_: U19.9(R2OUT) U28.12(VIC)
UART3_TX_DATA: U28.4(VIB) ; off-sheet UART3_TX_DATA  [also labelled UART3_TXD]
UART3_TXD_: U19.10(T2IN) U28.13(VOB)
NetC156_1: C156.1 U19.3(C1-)
NetC156_2: C156.2 U19.1(C1+)
NetC157_1: C157.1 U19.5(C2-)
NetC157_2: C157.2 U19.4(C2+)
NetC158_2: C158.2 U19.2(V+)
NetC159_2: C159.2 U19.6(V-)
NetC163_2: C163.2 R205.2 R206.2
NetD61_C: D61.C D63.1(I/O2) J22.1
NetD62_1: D62.1(I/O2) J22.2 R337.2
NetD80_A: D80.A(I/O2) D81.C(I/O1) F12.1 L42.2 R212.1
NetD80_C: D80.C(I/O1) D82.C(I/O1) F13.1 J33.2 L43.2
NetD85_C: D85.C(I/O1) D86.A(I/O2) F14.1 L44.2 R219.1
NetD86_C: D86.C(I/O1) D87.C(I/O1) F15.1 J59.2 L45.2
NetJ33_1: J33.1 R212.2
NetJ59_1: J59.1 R219.2
NetL36_2: L36.2 M2.2(VIN)
NetL37_1: L37.1 U19.14(T1OUT)
NetL38_1: L38.1 U19.13(R1IN)
NetL39_1: L39.1 U19.7(T2OUT)
NetL40_1: L40.1 U19.8(R2IN)
NetQ19_1: Q19.1(GATE) R345.1 R346.2
NetR324_2: R324.2 U24.1(RO)
NetR325_2: R325.2 U24.4(DI)

Not connected (* = marked no-connect by the designer): U22 5(VIO/NC); U28 3(VIA) 7(NC1)* 10(NC2)* 14(VOA)

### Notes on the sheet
- DEBUG
- RS232
- CAN
- RS485

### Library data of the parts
C151 = C-0603: as C35 on sheet P06 SOM6ULX
C154 C161 = C-0402: as C48 on sheet P08 USB
C156-C159 C193-C195 = C-0402: as C59 on sheet P09 ETHERNET
C160 C164 = C-0603: Part Number: C020102120069; Part Name: 贴片电容; Manufacture: 三星¦国巨¦村田; PCB Footprint: C0603L; ERP Number: 1010200142; DSC1: ±10%; DSC3: X5R; ID: 69
C163 C192 = C-0402: as C61 on sheet P09 ETHERNET
C165 = C-0603: Manufacture: 三星¦国巨¦村田; Part Name: 贴片电容; Part Number: C020102120069; PCB Footprint: C0603L; ID: 69; DSC3: X5R; DSC1: ±10%; ERP Number: 1010200142
C167 = C-0402: as C47 on sheet P08 USB
C191 = C-1206: Part Number: C020103263826; Part Name: 贴片电容; Manufacture: 三星¦国巨¦村田; DSC1: ±10%; DSC3: X5R; ID: 79; PCB Footprint: C1206L
D61 = DI-XI-S: as D121 on sheet P07 SD_RTC
D62 D63 = DI-ESD: as D96 on sheet P06 SOM6ULX
D66-D68 D74 D76 = DI-TVS-D: ESD 0402; Manufacturer: INPAQ; Manufacture P/N: MLVG04021R0UV18; Part Number: C040602260005; Part Name: TVS; Manufacture: MDD¦伯恩半导体; PN Type: Varistor; ERP Number: 1010800028; DSC1: 双向; DSC2: Vrwm=12V; DSC3: VBR=13.3V; DSC4: Vc=19.9V; DSC5: Ipp=20.1A; DSC6: Ppp=400W; ID: 5
D69 D75 D80-D82 D85-D87 = DI-TVS-D: ESD 0402; Manufacturer: INPAQ; Manufacture P/N: MLVG04021R0UV18; Part Number: C040602260005; Manufacture: MDD¦伯恩半导体; Part Name: TVS; PN Type: Varistor; ID: 5; DSC6: Ppp=400W; DSC5: Ipp=20.1A; DSC4: Vc=19.9V; DSC3: VBR=13.3V; DSC2: Vrwm=12V; DSC1: 双向; ERP Number: 1010800028
D101-D103 = DI-5TS075L_0: Manufacture: 良胜; Part Number: C040702270001; Part Name: 放电管; ID: 1; DSC4: SMD,5x7.6mm; DSC3: 5KA; DSC2: ±20%; DSC1: 75V; ERP Number: 1040100102
D105 = DI-5TS075L_0: Part Name: 放电管; Part Number: C040702270001; Manufacture: 良胜; ERP Number: 1040100102; DSC1: 75V; DSC2: ±20%; DSC3: 5KA; DSC4: SMD,5x7.6mm; ID: 1
D110 = DI-TVS-D: ESD 0402; Manufacturer: INPAQ; Manufacture P/N: MLVG04021R0UV18; Part Number: C040602260012; Part Name: TVS; Manufacture: MDD¦伯恩半导体; PN Type: Varistor; DSC1: 双向; DSC2: Vrwm=40V; DSC3: VBR=44.4V; DSC4: Vc=64.5V; DSC5: Ipp=9.3A; DSC6: Ppp=800W; ID: 12
F6-F10 F12 F13 = FUSE-SMD1206: Part Number: C160102670005; Part Name: 自恢复保险丝; Manufacture: BOURNS¦金科; DSC1: 60V; DSC2: 0.1A; DSC3: SMD1206P010TF; DSC4: JK-NSMD010; ID: 5
F11 F14 F15 = FUSE-SMD1206: Manufacture: BOURNS¦金科; Part Name: 自恢复保险丝; Part Number: C160102670005; ID: 5; DSC4: JK-NSMD010; DSC3: SMD1206P010TF; DSC2: 0.1A; DSC1: 60V
J9 = J-PCB-Con-12P: Part Number: J040204063841; Part Name: PCB插拔式接线端子; DSC1: 3.81mm间距; DSC2: 12P; DSC3: 通孔90度弯针; DSC4: 绿色; DSC5: WJ15EDGRC-3.81-12P(康奈克斯); ID: 50
J22 = J-A-3P_0: Part Number: J020102800040; ID: 2; DSC5: A1251WR-S-3P(CJT); DSC4: 米黄色胶壳 耐高温; DSC3: 卧贴; DSC2: 1.25mm间距; DSC1: 3p
J33 J59 = J-HDR-2: Part Number: J010204073842; Part Name: 单排针; DSC1: 单排单塑; DSC2: 1x2; DSC3: 2mm脚距; DSC4: 通孔直针; DSC5: 针长8.8mm  2.8+2(H塑高)+4 mm; DSC6: 黑胶; ID: 66
L36 = L-IND: Part Name: 功率电感; Part Number: C060202340017; Manufacture: 顺络; ERP Number: 1010200254; DSC1: ±20%; DSC2: Isat=0.65A; DSC3: Irms=0.5A; DSC4: 1.092Ω; DSC5: 2.5*2.0*1.0mm; DSC6: SWPA252010S100MT(顺络); ID: 17; Solder: 不推荐
L37-L40 L42 L43 = FB-0402: SMD Multilayer Ferrite Chip Bead,3A,30Ohm,0.03R; Part Number: C060502370001; Manufacture P/N: PZ1608D300-3R0TF; Manufacture2 P/N: PBY160808T-400Y-N; Manufacturer: SUNLORD; Part Name: 贴片磁珠; Manufacture: 顺络; PN Type: SMD FERRITE BEAD; ERP Number: 1010200208; DSC1: 120Ω@100MHz; DSC2: 200mA; DSC3: DCR=400mΩ; DSC4: 低频信号; ID: 1
L41 = L-CMLS-ACM2012: as L10 on sheet P08 USB
L44 L45 = FB-0402: SMD Multilayer Ferrite Chip Bead,3A,30Ohm,0.03R; Part Number: C060502370001; Manufacture P/N: PZ1608D300-3R0TF; Manufacture2 P/N: PBY160808T-400Y-N; Manufacturer: SUNLORD; Manufacture: 顺络; Part Name: 贴片磁珠; PN Type: SMD FERRITE BEAD; ID: 1; DSC4: 低频信号; DSC3: DCR=400mΩ; DSC2: 200mA; DSC1: 120Ω@100MHz; ERP Number: 1010200208
M2 = U-B0505S-1WR2_1: Part Number: C070502440002; Part Name: 电源模块; Manufacture: 金升阳; ERP Number: 1010100146; DSC1: Vi=4.5-5.5V; DSC2: Vo=5V; DSC3: 200mA; DSC4: 隔离型DC-DC; DSC5: 1.5KV隔离; ID: 2
Q19 = N-MOS: Part Number: C030202190006; Manufacture: 长电; ERP Number: 1010800035; DSC1: Vds=60V; DSC2: Id=115mA; DSC3: Vgs(th)=2.5V; DSC4: Vgs=±20V; DSC5: pd=200mW; ID: 6
R203 R216 R326 = R-0402: as R68 on sheet P08 USB
R204 = R-0402: Part Number: C011002080778; Part Name: 贴片电阻; ID: 778; DSC2: 1/16W; DSC1: ±1%
R205 R206 = R-0603: Part Name: 贴片电阻; Part Number: C011002081339; DSC1: ±1%; DSC2: 1/10W; ID: 1,339
R209 R217 R317 R333 = R-0402: as R43 on sheet P06 SOM6ULX
R210 R214 = R-0603: Part Name: 贴片电阻; Part Number: C011002081416; DSC1: ±1%; DSC2: 1/10W; ID: 1,416
R211 = R-0402: Part Name: 贴片电阻; Part Number: C011002080818; ERP Number: 1010200445; DSC1: ±1%; DSC2: 1/16W; ID: 818
R212 = R-1206: Part Name: 贴片电阻; Part Number: C011002081999; ERP Number: 1010200271; DSC1: ±1%; DSC2: 1/4W; ID: 1,999
R213 R215 R220 R222 = R-0402: as R56-R58 on sheet P07 SD_RTC
R218 R221 = R-0603: Part Number: C011002081416; Part Name: 贴片电阻; ID: 1,416; DSC2: 1/10W; DSC1: ±1%
R219 = R-1206: Part Number: C011002081999; Part Name: 贴片电阻; ID: 1,999; DSC2: 1/4W; DSC1: ±1%; ERP Number: 1010200271
R243 = R-0402: Part Name: 贴片电阻; Part Number: C011002080778; DSC1: ±1%; DSC2: 1/16W; ID: 778
R322 R323 = R-0402: Part Name: 贴片电阻; Part Number: C011002080413; DSC1: ±1%; DSC2: 1/16W; ID: 413
R324 R325 = R-0402: as R72 on sheet P08 USB
R334 R345 = R-0402: Part Name: 贴片电阻; Part Number: C011002080976; ERP Number: 1010200137; DSC1: ±1%; DSC2: 1/16W; ID: 976
R335 = R-0402: as R75 on sheet P08 USB
R337 = R-0402: Part Name: 贴片电阻; Part Number: C011002080630; ERP Number: 1010200450; DSC1: ±1%; DSC2: 1/16W; ID: 630
R346 = R-0402: Part Number: C011002081009; Part Name: 贴片电阻; ID: 1,009; DSC2: 1/16W; DSC1: ±1%; ERP Number: 1010200139
U19 = U-SP3232EEN-L-TR: Part Number: C100302510001; Part Name: RS232/RS485芯片; Manufacture: EXAR(艾科嘉); ERP Number: 1010100049; DSC1: RS232 Transceiver up to 235kbps; DSC2: SOIC-16_150mil，1.27mm Pitch; DSC3: -40℃~+85℃; ID: 22
U21 = U-122M31: Part Number: C100603313834; Part Name: 接口芯片; Manufacture: 荣湃; DSC1: 2路隔离芯片,3~5.5V，1发1收，3KV隔离，10Mbps; DSC2: SOIC-8_150mil，1.27mm Pitch; DSC3: -40℃~+125℃; ID: 44
U22 = U-TJA1057GT-3J: Manufacture: NXP; Part Name: CAN芯片; Part Number: C100402520002; ID: 27; DSC3: -40℃~+150℃; DSC2: SOIC-8_150mil，1.27mm Pitch; DSC1: CAN Transceiver, 5Mbps; ERP Number: 1010100240
U23 = U-SP485EEN-L-TR: Manufacture: EXAR(艾科嘉); Part Name: RS232/RS485芯片; Part Number: C100302510003; ID: 24; DSC3: -40℃~+85℃; DSC2: SOIC-8_150mil，1.27mm Pitch; DSC1: RS485 Transceiver ,up to 10Mbps; ERP Number: 1010100125
U24 = U-SP485EEN-L-TR: Part Number: C100302510003; Part Name: RS232/RS485芯片; Manufacture: EXAR(艾科嘉); ERP Number: 1010100125; DSC1: RS485 Transceiver ,up to 10Mbps; DSC2: SOIC-8_150mil，1.27mm Pitch; DSC3: -40℃~+85℃; ID: 24
U28 = U-142U31: Part Number: C100603283831; Part Name: 接口芯片; Manufacture: 荣湃; DSC1: 4路隔离芯片,3~5.5V，2发2收，3KV隔离，150Kbps; DSC2: SOP16 10*3.9*1.5mm 1.27mm Pitch; DSC3: -40℃~+125℃; ID: 41
U29 = U-162U31: Part Number: C100603303832; Part Name: 接口芯片; Manufacture: 荣湃; DSC1: 6路隔离芯片,3~5.5V，4发2收，3KV隔离，150Kbps; DSC2: SOP16 10*3.9*1.5mm 1.27mm Pitc; DSC3: -40℃~+125℃; ID: 43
